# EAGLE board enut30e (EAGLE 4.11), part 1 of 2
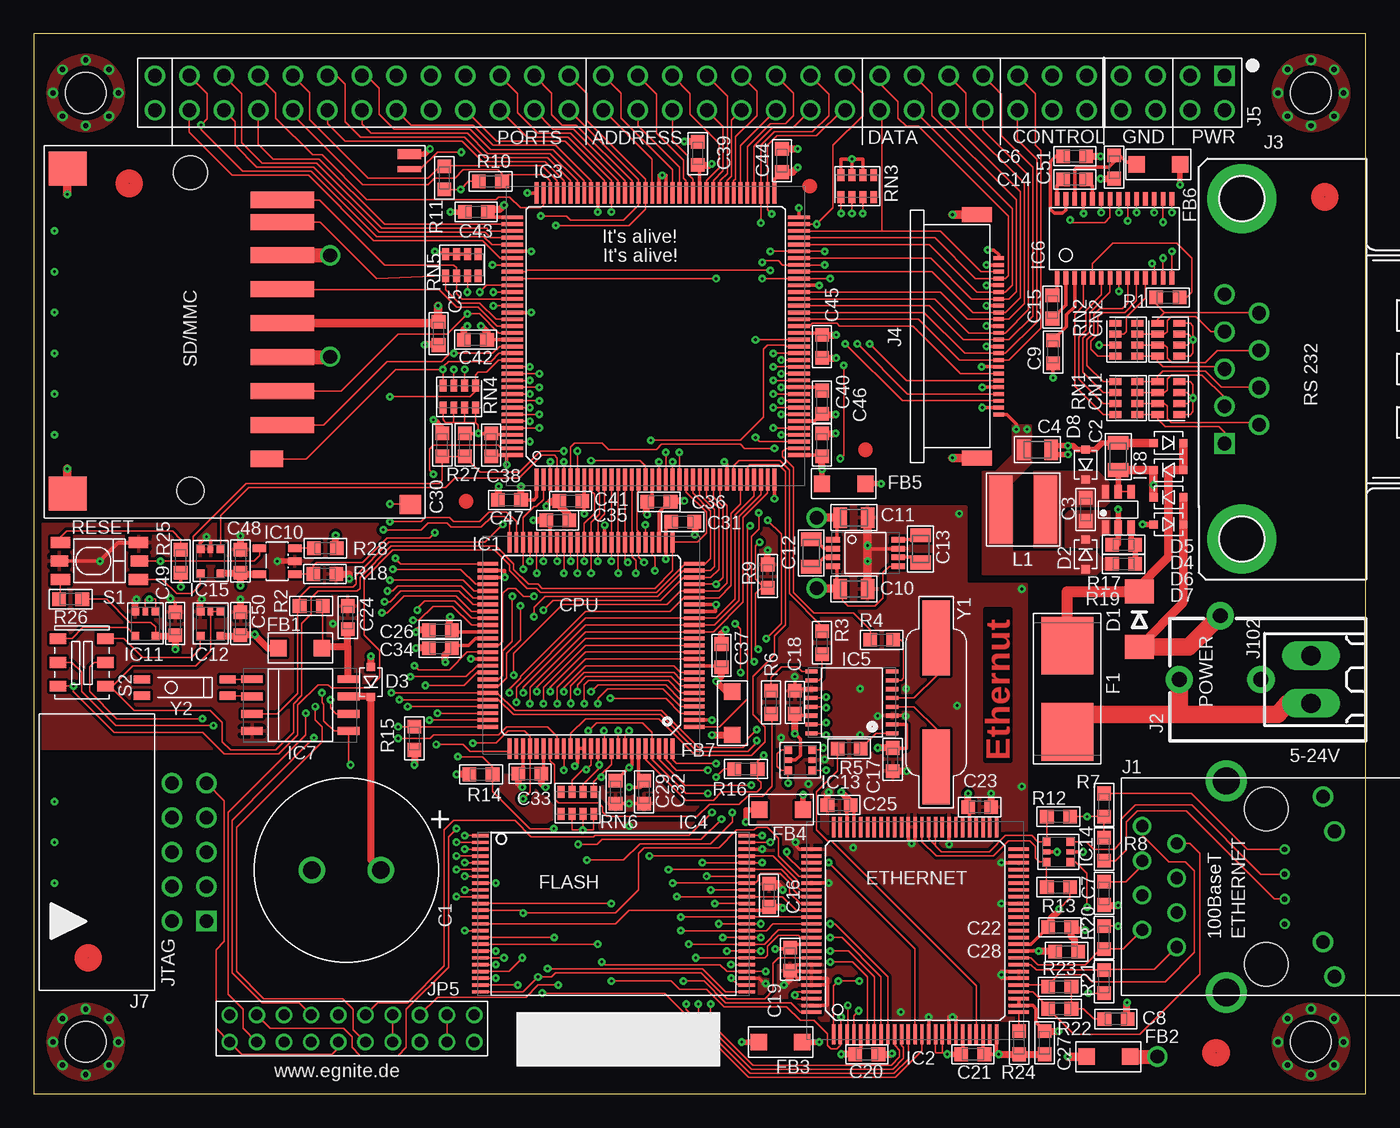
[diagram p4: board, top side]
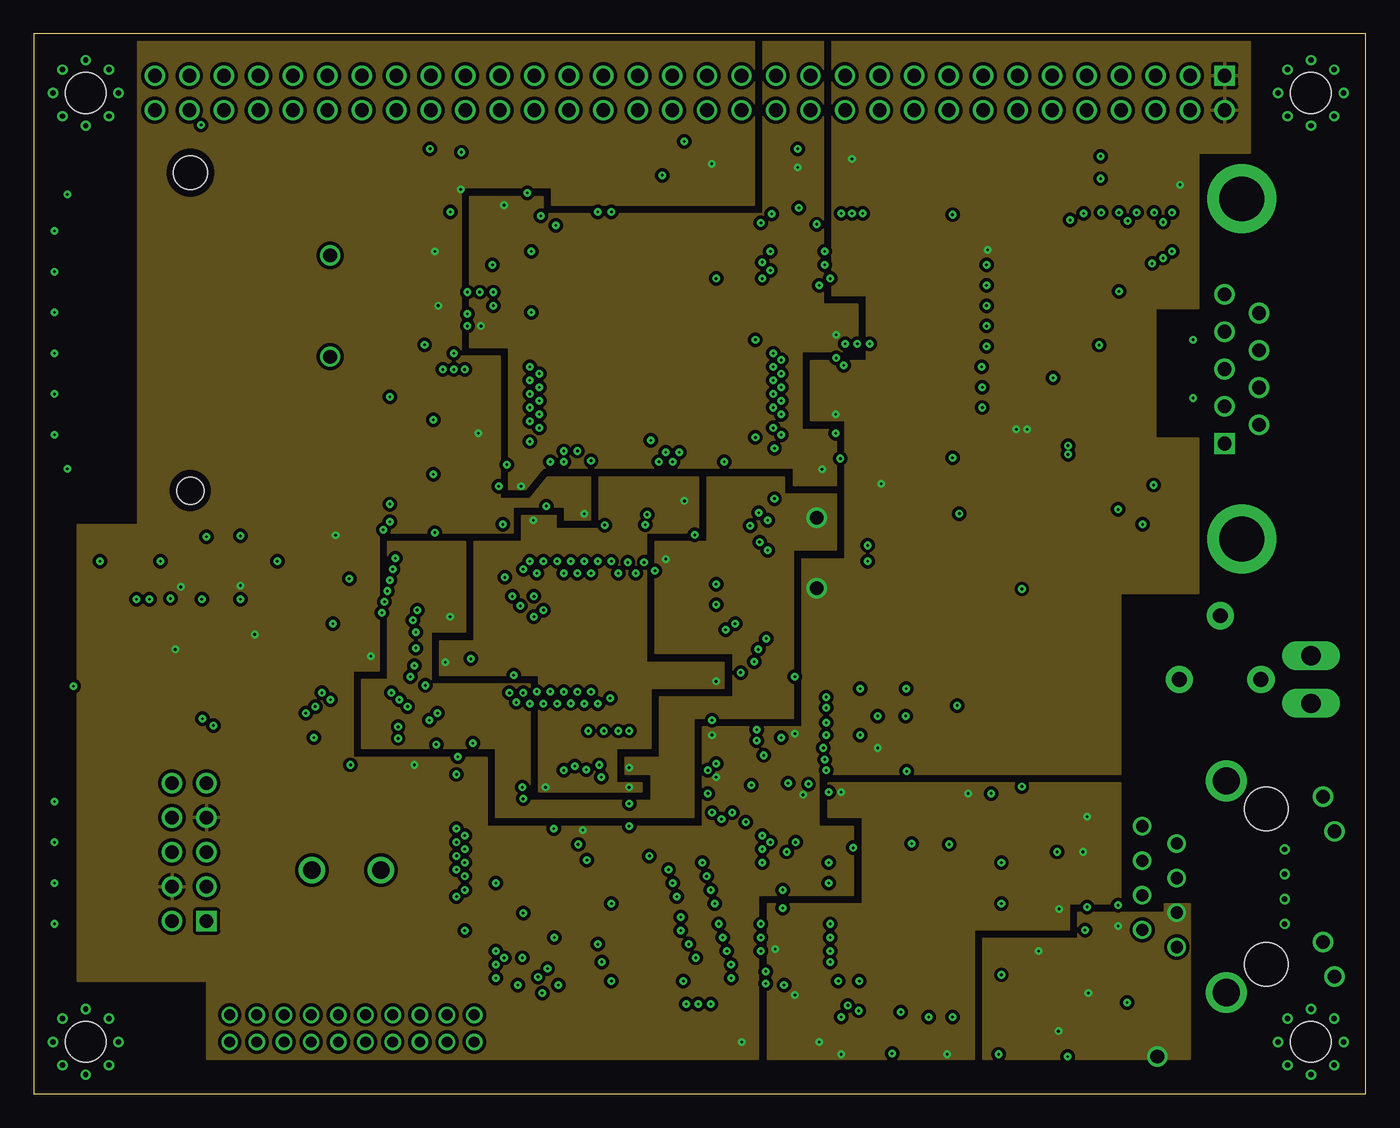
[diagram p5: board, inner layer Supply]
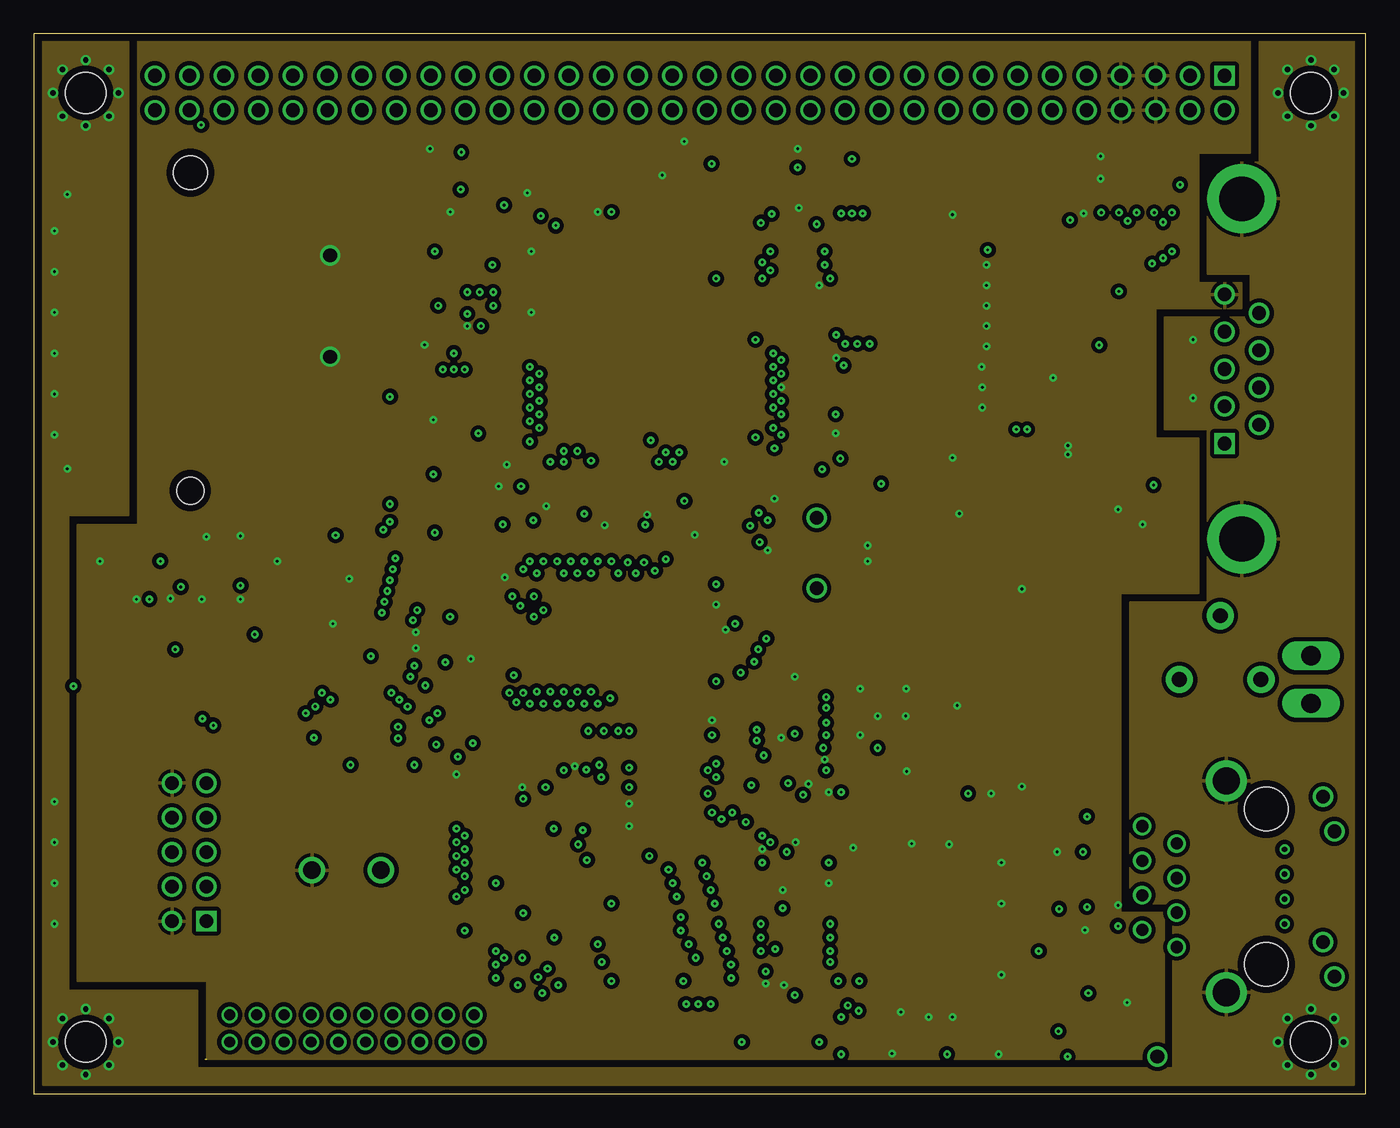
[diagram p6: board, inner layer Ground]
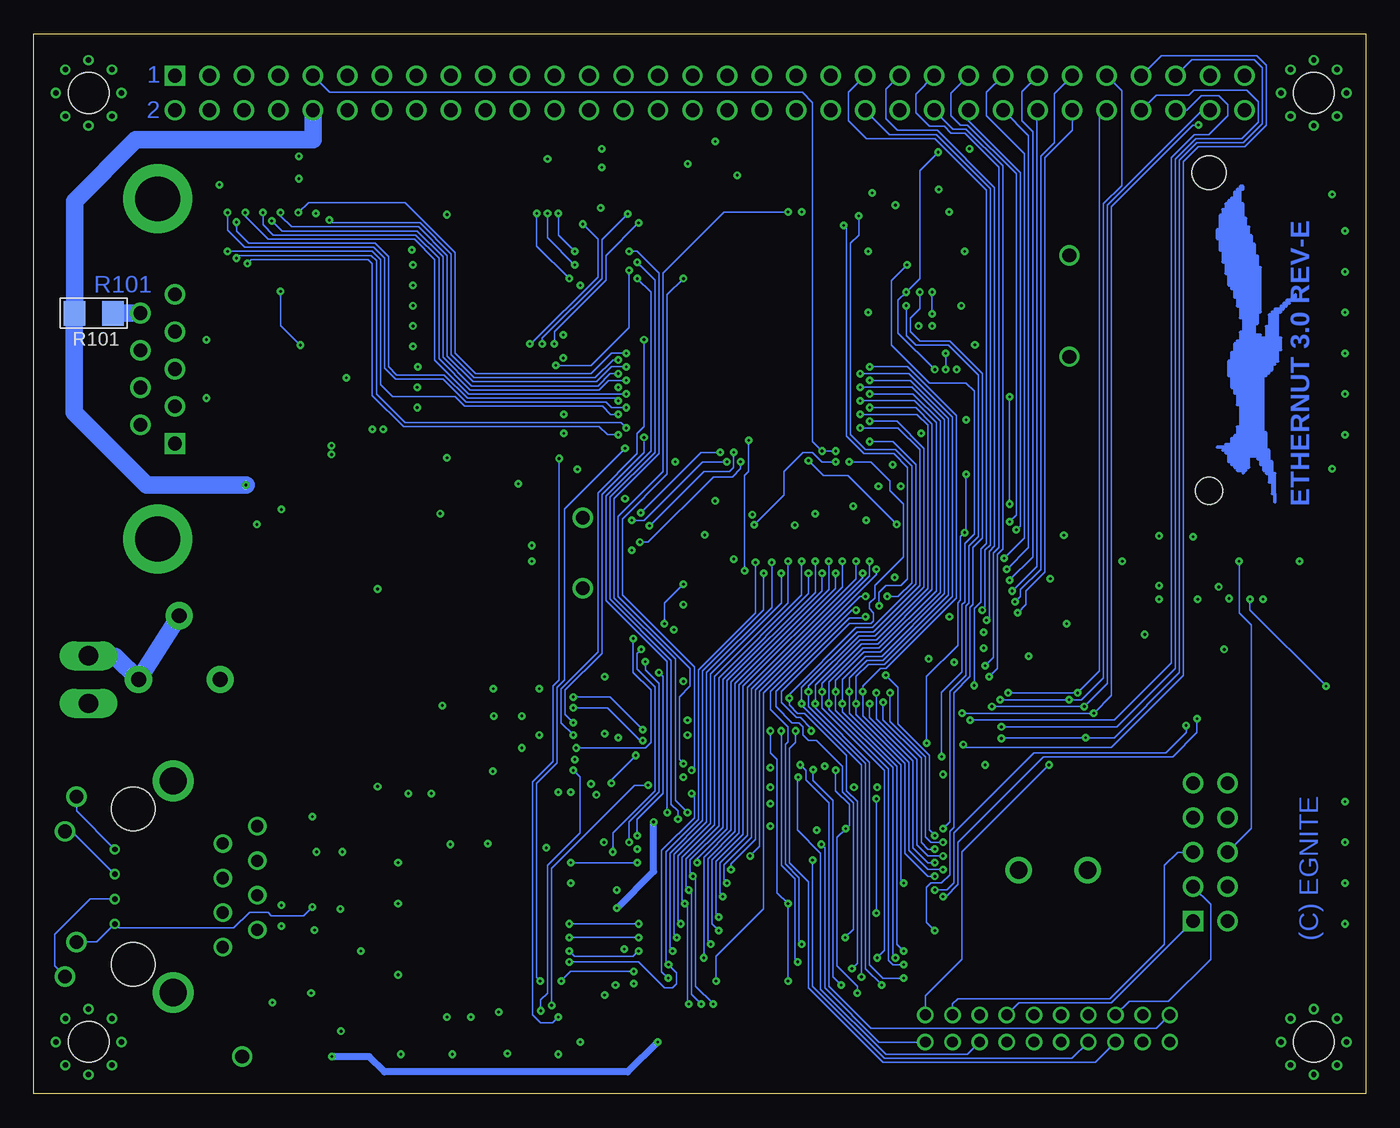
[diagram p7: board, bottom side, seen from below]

Size 98 x 78 mm. Coordinates in mm from the lower left corner, seen from the top.
Outline: 0,0 98,0 98,78 0,78 0,0
Copper layers (1*2+15*16): Top 0.035mm / dielectric 0.5mm / Supply 0.035mm / dielectric 0.5mm / Ground 0.035mm / dielectric 0.5mm / Bottom 0.035mm
Design rules "default": minimum track width 5mil, minimum drill 0.2mm, track to track 6mil, track to pad 6mil, pad to pad 8mil, via to via 8mil, smd to smd 8mil, copper to edge 20mil, drill to drill 12mil, minimum pad ring 8mil, minimum via ring 7mil, stop-mask expansion 0mil, vias tented up to drill 0.3mm, thermal gap 10mil
Net classes: 1 Supply1A: width 0.61 mm; 4 Ground: width 0.406 mm
Holes 3 mm at 3.81,73.66 93.98,73.66 3.81,3.81 93.98,3.81

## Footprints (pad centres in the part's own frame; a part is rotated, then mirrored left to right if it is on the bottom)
CDL13_5 = drill 1.3 pad 1.3 round: + 2.54,0; - -2.54,0
C0805 = smd 1 x 1.5: 1 -1,0; 2 1,0
C0603 = smd 1 x 1: 1 -0.85,0; 2 0.85,0
NCA1206 = smd 0.508 x 0.889: 1 -1.2,-0.805; 2 -0.4,-0.805; 3 0.4,-0.805; 4 1.2,-0.805; 5 1.2,0.805; 6 0.4,0.805; 7 -0.4,0.805; 8 -1.2,0.805
SMB = smd 1.778 x 2.159: A 2.032,0; C -2.032,0
SOD323 = smd 0.6 x 0.6: A 1.1,0; C -1.1,0
OMNI-BLOK = smd 4.242 x 3.81: 1 -3.175,0; 2 3.175,0
BLM31 = smd 1.2 x 1.2: 1 -1.6,0; 2 1.6,0
TQFP100 = smd 0.28 x 1.5: 1 -6,-7.6; 2 -5.5,-7.6; 3 -5,-7.6; 4 -4.5,-7.6; 5 -4,-7.6; 6 -3.5,-7.6; 7 -3,-7.6; 8 -2.5,-7.6; 9 -2,-7.6; 10 -1.5,-7.6; 11 -1,-7.6; 12 -0.5,-7.6; 13 0,-7.6; 14 0.5,-7.6; 15 1,-7.6; 16 1.5,-7.6; 17 2,-7.6; 18 2.5,-7.6; 19 3,-7.6; 20 3.5,-7.6; 21 4,-7.6; 22 4.5,-7.6; 23 5,-7.6; 24 5.5,-7.6; 25 6,-7.6; 51 6,7.6; 52 5.5,7.6; 53 5,7.6; 54 4.5,7.6; 55 4,7.6; 56 3.5,7.6; 57 3,7.6; 58 2.5,7.6; 59 2,7.6; 60 1.5,7.6; 61 1,7.6; 62 0.5,7.6; 63 0,7.6; 64 -0.5,7.6; 65 -1,7.6; 66 -1.5,7.6; 67 -2,7.6; 68 -2.5,7.6; 69 -3,7.6; 70 -3.5,7.6; 71 -4,7.6; 72 -4.5,7.6; 73 -5,7.6; 74 -5.5,7.6; 75 -6,7.6 | smd 1.5 x 0.28: 26 7.6,-6; 27 7.6,-5.5; 28 7.6,-5; 29 7.6,-4.5; 30 7.6,-4; 31 7.6,-3.5; 32 7.6,-3; 33 7.6,-2.5; 34 7.6,-2; 35 7.6,-1.5; 36 7.6,-1; 37 7.6,-0.5; 38 7.6,0; 39 7.6,0.5; 40 7.6,1; 41 7.6,1.5; 42 7.6,2; 43 7.6,2.5; 44 7.6,3; 45 7.6,3.5; 46 7.6,4; 47 7.6,4.5; 48 7.6,5; 49 7.6,5.5; 50 7.6,6; 76 -7.6,6; 77 -7.6,5.5; 78 -7.6,5; 79 -7.6,4.5; 80 -7.6,4; 81 -7.6,3.5; 82 -7.6,3; 83 -7.6,2.5; 84 -7.6,2; 85 -7.6,1.5; 86 -7.6,1; 87 -7.6,0.5; 88 -7.6,0; 89 -7.6,-0.5; 90 -7.6,-1; 91 -7.6,-1.5; 92 -7.6,-2; 93 -7.6,-2.5; 94 -7.6,-3; 95 -7.6,-3.5; 96 -7.6,-4; 97 -7.6,-4.5; 98 -7.6,-5; 99 -7.6,-5.5; 100 -7.6,-6
LQFP100 = smd 0.25 x 1.5: 1 -6,-7.625; 2 -5.5,-7.625; 3 -5,-7.625; 4 -4.5,-7.625; 5 -4,-7.625; 6 -3.5,-7.625; 7 -3,-7.625; 8 -2.5,-7.625; 9 -2,-7.625; 10 -1.5,-7.625; 11 -1,-7.625; 12 -0.5,-7.625; 13 0,-7.625; 14 0.5,-7.625; 15 1,-7.625; 16 1.5,-7.625; 17 2,-7.625; 18 2.5,-7.625; 19 3,-7.625; 20 3.5,-7.625; 21 4,-7.625; 22 4.5,-7.625; 23 5,-7.625; 24 5.5,-7.625; 25 6,-7.625; 51 6,7.625; 52 5.5,7.625; 53 5,7.625; 54 4.5,7.625; 55 4,7.625; 56 3.5,7.625; 57 3,7.625; 58 2.5,7.625; 59 2,7.625; 60 1.5,7.625; 61 1,7.625; 62 0.5,7.625; 63 0,7.625; 64 -0.5,7.625; 65 -1,7.625; 66 -1.5,7.625; 67 -2,7.625; 68 -2.5,7.625; 69 -3,7.625; 70 -3.5,7.625; 71 -4,7.625; 72 -4.5,7.625; 73 -5,7.625; 74 -5.5,7.625; 75 -6,7.625 | smd 1.5 x 0.25: 26 7.625,-6; 27 7.625,-5.5; 28 7.625,-5; 29 7.625,-4.5; 30 7.625,-4; 31 7.625,-3.5; 32 7.625,-3; 33 7.625,-2.5; 34 7.625,-2; 35 7.625,-1.5; 36 7.625,-1; 37 7.625,-0.5; 38 7.625,0; 39 7.625,0.5; 40 7.625,1; 41 7.625,1.5; 42 7.625,2; 43 7.625,2.5; 44 7.625,3; 45 7.625,3.5; 46 7.625,4; 47 7.625,4.5; 48 7.625,5; 49 7.625,5.5; 50 7.625,6; 76 -7.625,6; 77 -7.625,5.5; 78 -7.625,5; 79 -7.625,4.5; 80 -7.625,4; 81 -7.625,3.5; 82 -7.625,3; 83 -7.625,2.5; 84 -7.625,2; 85 -7.625,1.5; 86 -7.625,1; 87 -7.625,0.5; 88 -7.625,0; 89 -7.625,-0.5; 90 -7.625,-1; 91 -7.625,-1.5; 92 -7.625,-2; 93 -7.625,-2.5; 94 -7.625,-3; 95 -7.625,-3.5; 96 -7.625,-4; 97 -7.625,-4.5; 98 -7.625,-5; 99 -7.625,-5.5; 100 -7.625,-6
XC95_TQ144 = smd 0.28 x 1.6: 1 -8.75,-10.55; 2 -8.25,-10.55; 3 -7.75,-10.55; 4 -7.25,-10.55; 5 -6.75,-10.55; 6 -6.25,-10.55; 7 -5.75,-10.55; 8 -5.25,-10.55; 9 -4.75,-10.55; 10 -4.25,-10.55; 11 -3.75,-10.55; 12 -3.25,-10.55; 13 -2.75,-10.55; 14 -2.25,-10.55; 15 -1.75,-10.55; 16 -1.25,-10.55; 17 -0.75,-10.55; 18 -0.25,-10.55; 19 0.25,-10.55; 20 0.75,-10.55; 21 1.25,-10.55; 22 1.75,-10.55; 23 2.25,-10.55; 24 2.75,-10.55; 25 3.25,-10.55; 26 3.75,-10.55; 27 4.25,-10.55; 28 4.75,-10.55; 29 5.25,-10.55; 30 5.75,-10.55; 31 6.25,-10.55; 32 6.75,-10.55; 33 7.25,-10.55; 34 7.75,-10.55; 35 8.25,-10.55; 36 8.75,-10.55; 73 8.75,10.55; 74 8.25,10.55; 75 7.75,10.55; 76 7.25,10.55; 77 6.75,10.55; 78 6.25,10.55; 79 5.75,10.55; 80 5.25,10.55; 81 4.75,10.55; 82 4.25,10.55; 83 3.75,10.55; 84 3.25,10.55; 85 2.75,10.55; 86 2.25,10.55; 87 1.75,10.55; 88 1.25,10.55; 89 0.75,10.55; 90 0.25,10.55; 91 -0.25,10.55; 92 -0.75,10.55; 93 -1.25,10.55; 94 -1.75,10.55; 95 -2.25,10.55; 96 -2.75,10.55; 97 -3.25,10.55; 98 -3.75,10.55; 99 -4.25,10.55; 100 -4.75,10.55; 101 -5.25,10.55; 102 -5.75,10.55; 103 -6.25,10.55; 104 -6.75,10.55; 105 -7.25,10.55; 106 -7.75,10.55; 107 -8.25,10.55; 108 -8.75,10.55 | smd 1.6 x 0.28: 37 10.55,-8.75; 38 10.55,-8.25; 39 10.55,-7.75; 40 10.55,-7.25; 41 10.55,-6.75; 42 10.55,-6.25; 43 10.55,-5.75; 44 10.55,-5.25; 45 10.55,-4.75; 46 10.55,-4.25; 47 10.55,-3.75; 48 10.55,-3.25; 49 10.55,-2.75; 50 10.55,-2.25; 51 10.55,-1.75; 52 10.55,-1.25; 53 10.55,-0.75; 54 10.55,-0.25; 55 10.55,0.25; 56 10.55,0.75; 57 10.55,1.25; 58 10.55,1.75; 59 10.55,2.25; 60 10.55,2.75; 61 10.55,3.25; 62 10.55,3.75; 63 10.55,4.25; 64 10.55,4.75; 65 10.55,5.25; 66 10.55,5.75; 67 10.55,6.25; 68 10.55,6.75; 69 10.55,7.25; 70 10.55,7.75; 71 10.55,8.25; 72 10.55,8.75; 109 -10.55,8.75; 110 -10.55,8.25; 111 -10.55,7.75; 112 -10.55,7.25; 113 -10.55,6.75; 114 -10.55,6.25; 115 -10.55,5.75; 116 -10.55,5.25; 117 -10.55,4.75; 118 -10.55,4.25; 119 -10.55,3.75; 120 -10.55,3.25; 121 -10.55,2.75; 122 -10.55,2.25; 123 -10.55,1.75; 124 -10.55,1.25; 125 -10.55,0.75; 126 -10.55,0.25; 127 -10.55,-0.25; 128 -10.55,-0.75; 129 -10.55,-1.25; 130 -10.55,-1.75; 131 -10.55,-2.25; 132 -10.55,-2.75; 133 -10.55,-3.25; 134 -10.55,-3.75; 135 -10.55,-4.25; 136 -10.55,-4.75; 137 -10.55,-5.25; 138 -10.55,-5.75; 139 -10.55,-6.25; 140 -10.55,-6.75; 141 -10.55,-7.25; 142 -10.55,-7.75; 143 -10.55,-8.25; 144 -10.55,-8.75
TSOP48 = smd 0.25 x 1.2: 1 -5.75,-9.8; 2 -5.25,-9.8; 3 -4.75,-9.8; 4 -4.25,-9.8; 5 -3.75,-9.8; 6 -3.25,-9.8; 7 -2.75,-9.8; 8 -2.25,-9.8; 9 -1.75,-9.8; 10 -1.25,-9.8; 11 -0.75,-9.8; 12 -0.25,-9.8; 13 0.25,-9.8; 14 0.75,-9.8; 15 1.25,-9.8; 16 1.75,-9.8; 17 2.25,-9.8; 18 2.75,-9.8; 19 3.25,-9.8; 20 3.75,-9.8; 21 4.25,-9.8; 22 4.75,-9.8; 23 5.25,-9.8; 24 5.75,-9.8; 25 5.75,9.8; 26 5.25,9.8; 27 4.75,9.8; 28 4.25,9.8; 29 3.75,9.8; 30 3.25,9.8; 31 2.75,9.8; 32 2.25,9.8; 33 1.75,9.8; 34 1.25,9.8; 35 0.75,9.8; 36 0.25,9.8; 37 -0.25,9.8; 38 -0.75,9.8; 39 -1.25,9.8; 40 -1.75,9.8; 41 -2.25,9.8; 42 -2.75,9.8; 43 -3.25,9.8; 44 -3.75,9.8; 45 -4.25,9.8; 46 -4.75,9.8; 47 -5.25,9.8; 48 -5.75,9.8
TSSOP16 = smd 0.3 x 0.9: 1 -2.275,-2.97; 2 -1.625,-2.97; 3 -0.975,-2.97; 4 -0.325,-2.97; 5 0.325,-2.97; 6 0.975,-2.97; 7 1.625,-2.97; 8 2.275,-2.97; 9 2.275,2.97; 10 1.625,2.97; 11 0.975,2.97; 12 0.325,2.97; 13 -0.325,2.97; 14 -0.975,2.97; 15 -1.625,2.97; 16 -2.275,2.97
TSSOP28 = smd 0.35 x 1: 1 -4.225,-2.918; 2 -3.575,-2.918; 3 -2.925,-2.918; 4 -2.275,-2.918; 5 -1.625,-2.918; 6 -0.975,-2.918; 7 -0.325,-2.918; 8 0.325,-2.918; 9 0.975,-2.918; 10 1.625,-2.918; 11 2.275,-2.918; 12 2.925,-2.918; 13 3.575,-2.918; 14 4.225,-2.918; 15 4.225,2.918; 16 3.575,2.918; 17 2.925,2.918; 18 2.275,2.918; 19 1.625,2.918; 20 0.975,2.918; 21 0.325,2.918; 22 -0.325,2.918; 23 -0.975,2.918; 24 -1.625,2.918; 25 -2.275,2.918; 26 -2.925,2.918; 27 -3.575,2.918; 28 -4.225,2.918
SOIC-8-209 = smd 0.58 x 1.6: 1 -1.905,-3.556; 2 -0.635,-3.556; 3 0.635,-3.556; 4 1.905,-3.556; 5 1.905,3.556; 6 0.635,3.556; 7 -0.635,3.556; 8 -1.905,3.556
TSOT-23-6 = smd 0.54 x 1: 1 -0.95,-1.31; 2 0,-1.31; 3 0.95,-1.31; 4 0.95,1.31; 5 0,1.31; 6 -0.95,1.31
MSOP-8 = smd 0.41 x 1.02: 1 -0.975,-2.4; 2 -0.325,-2.4; 3 0.325,-2.4; 4 0.975,-2.4; 5 0.975,2.4; 6 0.325,2.4; 7 -0.325,2.4; 8 -0.975,2.4
SOT23-5L = smd 0.55 x 0.99: 1 -0.95,-1.3; 2 0,-1.3; 3 0.95,-1.3; 4 0.95,1.3; 5 -0.95,1.3
SOT353 = smd 0.6 x 0.6: 1 -0.75,-0.9; 3 0.75,-0.9; 4 0.75,0.9; 5 -0.75,0.9 | smd 0.4 x 0.6: 2 0,-0.9
SOT363 = smd 0.6 x 0.6: 1 -0.75,-0.9; 3 0.75,-0.9; 4 0.75,0.9; 6 -0.75,0.9 | smd 0.4 x 0.6: 2 0,-0.9; 5 0,0.9
RJLD-043TC = drill 0.9 round: 1 -6.7,-4.445; 2 -9.24,-3.175; 3 -6.7,-1.905; 4 -9.24,-0.635; 5 -6.7,0.635; 6 -9.24,1.905; 7 -6.7,3.175; 8 -9.24,4.445 | drill 1 round: 9 4.9,-6.61; 10 4.06,-4.07; 11 4.9,4.07; 12 4.06,6.61 | drill 2 round: S1 -3.05,-7.79; S2 -3.05,7.79 | hole 3.2: -0.102,-5.715; -0.102,5.715
TDC-002-3 = drill 1.1 pad 2 round: 1 -6.5,0; 2 -0.5,0; 3 -3.5,4.7
M09HP = drill 1.016 square: 1 -5.486,5.08 | drill 1.016 round: 2 -2.743,5.08; 3 0,5.08; 4 2.743,5.08; 5 5.486,5.08; 6 -4.115,2.54; 7 -1.372,2.54; 8 1.372,2.54; 9 4.115,2.54 | drill 3.302 pad 5.08 round: G1 -12.522,3.81; G2 12.522,3.81
FFC-52437 = smd 0.29 x 0.8: 1 -5.75,3.5; 2 -5.25,3.5; 3 -4.75,3.5; 4 -4.25,3.5; 5 -3.75,3.5; 6 -3.25,3.5; 7 -2.75,3.5; 8 -2.25,3.5; 9 -1.75,3.5; 10 -1.25,3.5; 11 -0.75,3.5; 12 -0.25,3.5; 13 0.25,3.5; 14 0.75,3.5; 15 1.25,3.5; 16 1.75,3.5; 17 2.25,3.5; 18 2.75,3.5; 19 3.25,3.5; 20 3.75,3.5; 21 4.25,3.5; 22 4.75,3.5; 23 5.25,3.5; 24 5.75,3.5 | smd 1.1 x 2.2: G1 -8.95,1.9; G2 8.95,1.9
NUTEXP = drill 1 square: 1 39.37,1.27 | drill 1 round: 2 39.37,-1.27; 3 36.83,1.27; 4 36.83,-1.27; 5 34.29,1.27; 6 34.29,-1.27; 7 31.75,1.27; 8 31.75,-1.27; 9 29.21,1.27; 10 29.21,-1.27; 11 26.67,1.27; 12 26.67,-1.27; 13 24.13,1.27; 14 24.13,-1.27; 15 21.59,1.27; 16 21.59,-1.27; 17 19.05,1.27; 18 19.05,-1.27; 19 16.51,1.27; 20 16.51,-1.27; 21 13.97,1.27; 22 13.97,-1.27; 23 11.43,1.27; 24 11.43,-1.27; 25 8.89,1.27; 26 8.89,-1.27; 27 6.35,1.27; 28 6.35,-1.27; 29 3.81,1.27; 30 3.81,-1.27; 31 1.27,1.27; 32 1.27,-1.27; 33 -1.27,1.27; 34 -1.27,-1.27; 35 -3.81,1.27; 36 -3.81,-1.27; 37 -6.35,1.27; 38 -6.35,-1.27; 39 -8.89,1.27; 40 -8.89,-1.27; 41 -11.43,1.27; 42 -11.43,-1.27; 43 -13.97,1.27; 44 -13.97,-1.27; 45 -16.51,1.27; 46 -16.51,-1.27; 47 -19.05,1.27; 48 -19.05,-1.27; 49 -21.59,1.27; 50 -21.59,-1.27; 51 -24.13,1.27; 52 -24.13,-1.27; 53 -26.67,1.27; 54 -26.67,-1.27; 55 -29.21,1.27; 56 -29.21,-1.27; 57 -31.75,1.27; 58 -31.75,-1.27; 59 -34.29,1.27; 60 -34.29,-1.27; 61 -36.83,1.27; 62 -36.83,-1.27; 63 -39.37,1.27; 64 -39.37,-1.27
FPS009-2700 = smd 4.7 x 1.2: 1 -3.51,6.85; 2 -3.51,4.35; 3 -3.51,1.85; 4 -3.51,-0.65; 5 -3.51,-3.15; 6 -3.51,-5.65; 7 -3.51,-8.08; 8 -3.51,-9.71 | smd 2.4 x 1.2: 9 -2.36,9.35 | smd 1.75 x 0.75: C -12.865,-13.09 | smd 1.75 x 0.45: CD -12.865,-11.965 | smd 2.8 x 2.5: CH1 12.29,11.91; CH2 12.29,-12 | smd 1.6 x 1.4: WP -12.94,12.71 | hole 2: 3.26,11.68 | hole 2.5: 3.26,-11.72
ML10A = drill 1 pad 1.422 square: 1 -5.08,-6.35 | drill 1 pad 1.422 round: 2 -5.08,-3.81; 3 -2.54,-6.35; 4 -2.54,-3.81; 5 0,-6.35; 6 0,-3.81; 7 2.54,-6.35; 8 2.54,-3.81; 9 5.08,-6.35; 10 5.08,-3.81
180-2 = drill 1.422 long: 1 -1.75,0; 2 1.75,0
JP10X2 = drill 0.8 round: 1 -9,-1; 2 -9,1; 3 -7,-1; 4 -7,1; 5 -5,-1; 6 -5,1; 7 -3,-1; 8 -3,1; 9 -1,-1; 10 -1,1; 11 1,-1; 12 1,1; 13 3,-1; 14 3,1; 15 5,-1; 16 5,1; 17 7,-1; 18 7,1; 19 9,-1; 20 9,1
MSS5131 = smd 5 x 1.7: 1 0,-1.65; 2 0,1.65
R0603 = smd 1 x 1: 1 -0.85,0; 2 0.85,0
R1206 = smd 1.6 x 1.803: 1 -1.422,0; 2 1.422,0
CAY16 = smd 0.508 x 0.889: 1 -1.2,-0.805; 2 -0.4,-0.805; 3 0.4,-0.805; 4 1.2,-0.805; 5 1.2,0.805; 6 0.4,0.805; 7 -0.4,0.805; 8 -1.2,0.805
PTS-026 = smd 1.45 x 0.8: A1 2.875,-1.35; A2 2.875,1.35; C1 -2.875,-1.35; C2 -2.875,1.35 | smd 1.3 x 0.8: S1 2.95,0; S2 -2.95,0
CAS-D20A1 = smd 0.8 x 1.2: 1 -1.75,-1.75; 2 0,-1.75; 3 1.75,-1.75; 4 -1.75,1.75; 5 0,1.75; 6 1.75,1.75
HC49SM = smd 5.5 x 2: 1 -4.75,0; 2 4.75,0
MC-146 = smd 1.2 x 0.6: 1 -3.15,-0.6; 2 3.15,-0.6; 3 3.15,0.6; 4 -3.15,0.6

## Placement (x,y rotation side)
C1  0.1F  [CDL13_5]  23,16.45 0 top
C2  1u  [C0805]  79.8,46.9 90 top
C3  10n  [C0603]  77.4,43 90 top
C4  10u  [C0805]  73.85,47.4 0 top
C5  470n  [C0603]  29.78,55.95 270 top
C6  470n  [C0603]  76.6,69 0 top
C7  100n  [C0603]  78.75,14.75 270 top
C8  100n  [C0603]  79.62,5.5 0 top
C9  470n  [C0603]  75,54.6 270 top
C10  10u  [C0805]  60.35,37.15 0 top
C11  10u  [C0805]  60.35,42.4 0 top
C12  1u  [C0805]  57.2,39.8 90 top
C13  1u  [C0805]  65.25,40.1 90 top
C14  100n  [C0603]  76.6,67.3 0 top
C15  470n  [C0603]  74.95,57.9 270 top
C16  100n  [C0603]  54.1,14.6 90 top
C17  100n  [C0603]  63.2,24.6 270 top
C18  100n  [C0603]  56,28.8 90 top
C19  100n  [C0603]  55.65,9.9 270 top
C20  100n  [C0603]  61.3,2.9 0 top
C21  100n  [C0603]  69.1,2.9 0 top
C22  100n  [C0603]  75.5,12.25 0 top
C23  100n  [C0603]  69.6,21.1 0 top
C24  100n  [C0603]  23.1,35.05 90 top
C25  100n  [C0603]  59.25,21.25 180 top
C26  100n  [C0603]  29.9,34.12 180 top
C27  100n  [C0603]  74.38,3.75 270 top
C28  100n  [C0603]  76,10.45 0 top
C29  100n  [C0603]  42.8,22.2 270 top
C30  100n  [C0603]  30.05,47.75 90 top
C31  100n  [C0603]  47.75,42.1 0 top
C32  100n  [C0603]  44.9,22.2 270 top
C33  100n  [C0603]  36.5,23.55 180 top
C34  100n  [C0603]  29.9,32.8 180 top
C35  100n  [C0603]  38.55,42.2 0 top
C36  100n  [C0603]  46,43.58 180 top
C37  100n  [C0603]  50.6,32.25 90 top
C38  100n  [C0603]  33.65,47.75 270 top
C39  100n  [C0603]  48.85,69.2 90 top
C40  100n  [C0603]  58,50.9 90 top
C41  100n  [C0603]  39.5,43.62 180 top
C42  100n  [C0603]  32.5,55.5 180 top
C43  100n  [C0603]  32.55,64.9 180 top
C44  100n  [C0603]  55.05,68.67 90 top
C45  100n  [C0603]  58,55 270 top
C46  100n  [C0603]  58,47.75 90 top
C47  100n  [C0603]  35,43.7 180 top
C48  100n  [C0603]  15.2,39.2 90 top
C49  100n  [C0603]  10.4,34.6 90 top
C50  100n  [C0603]  15.2,34.6 90 top
C51  100n  [C0603]  79.5,68.2 270 top
CN1  220p  [NCA1206]  83.5,51.2 90 top
CN2  220p  [NCA1206]  83.5,55.5 270 top
D1  SM6T24CA  [SMB]  81.35,34.92 270 top
D2  PMEG3005AEA  [SOD323]  77.4,39.7 270 top
D3  PMEG2005AEA  [SOD323]  24.8,30.3 90 top
D4  PMEG3005AEA  [SOD323]  83.5,45.9 0 top
D5  PMEG3005AEA  [SOD323]  83.5,47.9 180 top
D6  PMEG3005AEA  [SOD323]  83.5,43.9 0 top
D7  PMEG3005AEA  [SOD323]  83.5,41.9 180 top
D8  PMEG3005AEA  [SOD323]  77.4,46.3 90 top
F1  1A  [OMNI-BLOK]  76.05,29.8 90 top
FB1  BLM31AJ601  [BLM31]  19.6,32.8 0 top
FB2  BLM31AJ601  [BLM31]  79.08,2.73 180 top
FB3  BLM31AJ601  [BLM31]  54.95,3.8 180 top
FB4  BLM31AJ601  [BLM31]  55,20.9 0 top
FB5  BLM31AJ601  [BLM31]  59.6,44.9 0 top
FB6  BLM31AJ601  [BLM31]  82.75,68.4 0 top
FB7  BLM31AJ601  [BLM31]  51.4,28 270 top
FM1  FIDUCIAL-2MM  [FIDUCIAL-2MM]  4,10 0 top
FM2  FIDUCIAL-2MM  [FIDUCIAL-2MM]  87,3 0 top
FM3  FIDUCIAL-2MM  [FIDUCIAL-2MM]  7,67 0 top
FM4  FIDUCIAL-2MM  [FIDUCIAL-2MM]  95,66 0 top
IC1  AT91R40008  [TQFP100]  41,33 90 top
IC2  DM9000E  [LQFP100]  64.85,12 0 top
IC3  XC95144XLTQ144  [XC95_TQ144]  45.75,55.75 0 top
IC4  AT49BV322A-70TI  [TSOP48]  42.65,13.25 270 top
IC5  CY22393  [TSSOP16]  60.2,28.8 90 top
IC6  MAX3243UI  [TSSOP28]  79.52,62.95 0 top
IC7  X1286A8  [SOIC-8-209]  19.6,28.6 270 top
IC8  LT1616  [TSOT-23-6]  79.8,43 0 top
IC9  LM2788MM-1.8  [MSOP-8]  61.2,39.8 270 top
IC10  MIC2775-46BM5  [SOT23-5L]  17.9,39.2 90 top
IC11  74LVC1G00GW  [SOT353]  8.2,34.6 180 top
IC12  74LVC1G00GW  [SOT353]  13,34.6 180 top
IC13  NC7WZ07P6X  [SOT363]  56.4,24.55 90 top
IC14  NC7WZ07P6X  [SOT363]  75.4,17.8 270 top
IC15  74LVC1G125GW  [SOT353]  13,39.2 180 top
J1  RJLD-043TC  [RJLD-043TC]  90.81,15.24 0 top
J2  2mm  [TDC-002-3]  90.81,30.48 0 top
J3  M09HP  [M09HP]  92.71,53.34 90 top
J4  FCC24  [FFC-52437]  67.5,55.75 270 top
J5  [NUTEXP]  48.26,73.66 0 top
J6  FPS009-2700  [FPS009-2700]  14.77,56.07 180 top
J7  [ML10A]  6.35,17.78 90 top
J102  [180-2]  93.98,30.48 90 top
JP5  JP10X2  [JP10X2]  23.4,4.8 180 top
L1  10u  [MSS5131]  72.8,43 270 top
LOGO  [LOGO]  5.17,43.52 90 bottom
R1  0  [R0603]  83.45,58.6 0 top
R2  10k  [R0603]  20.4,35.9 0 top
R3  22  [R0603]  58,33.2 90 top
R4  22  [R0603]  62.4,33.4 180 top
R5  22  [R0603]  60,25.4 180 top
R6  22  [R0603]  54.25,28.8 270 top
R7  180  [R0603]  78.75,21.25 270 top
R8  180  [R0603]  78.75,18 90 top
R9  1k  [R0603]  54,38.1 270 top
R10  10k  [R0603]  33.6,67.15 0 top
R11  10k  [R0603]  30.2,67.4 90 top
R12  10k  [R0603]  75.4,20.4 0 top
R13  10k  [R0603]  75.4,15.2 0 top
R14  10k  [R0603]  32.9,23.5 0 top
R15  100k  [R0603]  28,26.15 90 top
R16  10k  [R0603]  52.4,23.9 0 top
R17  10k 1%  [R0603]  80.2,40.4 0 top
R18  100k  [R0603]  21.4,38.25 0 top
R19  16.5k 1%  [R0603]  80.2,39 180 top
R20  50 1%  [R0603]  78.75,11.5 90 top
R21  50 1%  [R0603]  78.75,8.25 270 top
R22  50 1%  [R0603]  75.5,6.25 180 top
R23  50 1%  [R0603]  75.5,7.88 180 top
R24  6.8k 1%  [R0603]  72.5,3.75 90 top
R25  180  [R0603]  10.8,39.2 270 top
R26  180  [R0603]  2.7,36.4 0 top
R27  10k  [R0603]  31.7,47.75 90 top
R28  100k  [R0603]  21.45,40.15 0 top
R101  0  [R1206]  93.6,57.45 180 bottom
RN1  22  [CAY16]  80.4,51.2 270 top
RN2  22  [CAY16]  80.4,55.5 270 top
RN3  100k  [CAY16]  60.6,66.8 0 top
RN4  10k  [CAY16]  31.3,51.3 180 top
RN5  10k  [CAY16]  31.5,61 0 top
RN6  100k  [CAY16]  40,21.4 180 top
S1  SW-LED  [PTS-026]  4.82,39.21 180 top
S2  CAS-D20A1  [CAS-D20A1]  3.52,31.74 270 top
U$10  [MARK1]  31.8,43.6 0 top
U$13  [MARK1]  57.1,66.8 0 top
U$14  [MARK1]  61.2,47.4 0 top
Y1  25MHz  [HC49SM]  66.4,28.8 270 top
Y2  32.768kHz  [MC-146]  11.1,29.9 180 top

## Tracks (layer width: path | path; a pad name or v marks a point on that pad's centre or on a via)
A0  (via drill 0.2)
  Top 0.127: v52.7,41.8 52.5,41.6 52.5,29.05 50.45,27 IC1.1 | v46.5,47.2 46.5,47.15 | 46.5,47.15 IC3.20 | 46.5,47.15
  Bottom 0.127: v46.5,47.2 46.5,46.1 46.8,45.8 48.7,45.8 v52.7,41.8
A1  (via drill 0.2)
  Top 0.127: v36.5,48 IC3.142 | IC4.25 50.9,7.5 49.2,9.2 v37.8,9.2 | IC1.3 47.6,28 46.5,29.1 v42.4,29.1
  Bottom 0.127: v37.8,9.2 37.4,9.6 37.4,21.5 38.2,22.3 38.2,24.9 41.3,28 41.8,28 42.4,28.6 v42.4,29.1 42.4,29.4 37.5,34.3 36.3,34.3 33.1,37.5 33.1,46.3 34.8,48 v36.5,48
A2  (via drill 0.2)
  Top 0.127: IC1.4 47.6,28.5 46.3,29.8 42.2,29.8 41.5,29.1 v41.5,28.7 | IC2.92 54.8,10 54.4,9.6 54.4,7.6 53.8,7 51,7 49.1,8.9 38.4,8.9 38.1,8.6 v37.1,8.6 36,7.5 IC4.24 | v37.2,49 37,49 | 37,49 IC3.140 | 37,49
  Bottom 0.127: v37.2,49 34.4,49 32.8,47.4 32.8,37.4 36.2,34 37.4,34 41.5,29.9 v41.5,28.7 41.5,28.6 37.1,24.2 v37.1,8.6
A3  (via drill 0.2)
  Top 0.127: 34.85,49.5 | 34.85,49.5 IC3.139 | v36.5,49.5 34.85,49.5 | IC4.23 v35.6,8 | v41,29.58 41.52,30.1 46.5,30.1 47.6,29 IC1.5
  Bottom 0.127: v36.5,49.5 34.5,49.5 32.5,47.5 32.5,37.3 36.1,33.7 37.3,33.7 41,30 v41,29.58 41,28.5 36.8,24.3 36.8,9.2 v35.6,8
A4  (via drill 0.2)
  Top 0.127: 34.95,50 | 34.95,50 IC3.138 | v37.2,50 34.95,50 | IC4.22 | IC4.22 v34,8.5 | v40.5,28.7 40.5,30.1 40.8,30.4 46.7,30.4 47.6,29.5 IC1.6
  Bottom 0.127: v37.2,50 33,50 32.2,49.2 32.2,37.2 36,33.4 37.2,33.4 40.5,30.1 v40.5,28.7 40.5,28.4 36.5,24.4 36.5,9.5 35.5,8.5 v34,8.5
A5  (via drill 0.2)
  Top 0.127: 34.9,50.5 | 34.9,50.5 IC3.137 | v36.5,50.5 34.9,50.5 | IC1.7 47.6,30 46.9,30.7 40.6,30.7 40,30.1 v40,29.58 | IC4.21 34.95,9 v35.95,10
  Bottom 0.127: v36.5,50.5 33.1,50.5 31.9,49.3 31.9,37.1 35.9,33.1 37.1,33.1 40,30.2 v40,29.58 40,28.4 35.4,23.8 35.4,10.55 v35.95,10
A6  (via drill 0.2)
  Top 0.127: 34.95,51 | 34.95,51 IC3.136 | v37.2,51 34.95,51 | IC4.20 | IC4.20 v34,9.5 | IC1.8 47.6,30.5 47.1,31 40.5,31 39.5,30 v39.5,28.72
  Bottom 0.127: v37.2,51 33.2,51 31.6,49.4 31.6,37 35.8,32.8 37,32.8 39.5,30.3 v39.5,28.72 39.5,28.3 35.1,23.9 35.1,9.8 34.8,9.5 v34,9.5
A7  (via drill 0.2)
  Top 0.127: IC4.19 v34.6,10 | v39,29.58 39,29.9 40.6,31.5 47.1,31.5 47.6,31 IC1.9 | v36.5,51.5 36.45,51.5 | 36.45,51.5 IC3.135 | 36.45,51.5
  Bottom 0.127: v36.5,51.5 33.3,51.5 31.3,49.5 31.3,36.9 35.7,32.5 36.9,32.5 39,30.4 v39,29.58 39,28.2 34.8,24 34.8,10.2 v34.6,10
A8  (via drill 0.2)
  Top 0.127: 34.95,52 | 34.95,52 IC3.134 | v37.2,52 34.95,52 | IC4.18 | IC4.18 v34,10.5 | IC1.11 40.6,32 38.5,29.9 v38.5,28.7
  Bottom 0.127: v37.2,52 33.4,52 31,49.6 31,36.8 35.6,32.2 36.8,32.2 38.5,30.5 v38.5,28.7 | v38.5,28.7 38.5,28.1 34.5,24.1 34.5,11 v34,10.5 | v38.5,28.7 38.5,29.8
A9  (via drill 0.2)
  Top 0.127: 34.95,52.5 | 34.95,52.5 IC3.133 | v36.5,52.5 34.95,52.5 | IC1.12 40.6,32.5 38,29.9 v38,29.6 | IC4.8 | IC4.8 v34,15.5
  Bottom 0.127: v36.5,52.5 33.5,52.5 30.7,49.7 30.7,36.7 35.5,31.9 36.7,31.9 38,30.6 v38,29.6 38,28 34.2,24.2 34.2,15.7 v34,15.5
A10  (via drill 0.2)
  Top 0.127: IC4.7 v31.7,16 | IC1.13 40.6,33 37.5,29.9 v37.5,28.7 | v37.2,53 37.05,53 | 37.05,53 IC3.132 | 37.05,53
  Bottom 0.127: v31.7,16 32.2,16 33.9,17.7 33.9,24.3 37.5,27.9 v37.5,28.7 37.5,30.7 36.6,31.6 35.4,31.6 30.4,36.6 30.4,49.8 33.6,53 v37.2,53
A11  (via drill 0.2)
  Top 0.127: 31.45,16.5 v31.1,16.5 | IC4.6 31.45,16.5 | 31.45,16.5 | v36.5,53.5 36.15,53.5 | 36.15,53.5 IC3.131 | 36.15,53.5 | IC1.14 40.6,33.5 37,29.9 v37,29.6
  Bottom 0.127: v31.1,16.5 32.2,16.5 33.6,17.9 33.6,24.4 37,27.8 v37,29.6 37,30 35.7,31.3 35.3,31.3 30.1,36.5 30.1,49.9 33.7,53.5 v36.5,53.5
A12  (via drill 0.2)
  Top 0.127: IC3.35 54,44.2 52.2,42.4 52.2,36.2 50,34 IC1.15 40.6,34 36.5,29.9 v36.5,28.7 | IC4.5 v31.7,17
  Bottom 0.127: v31.7,17 32.2,17 33.3,18.1 33.3,24.5 36.5,27.7 v36.5,28.7
A13  (via drill 0.2)
  Top 0.127: IC3.34 53.5,44.1 51.9,42.5 51.9,36.3 50.1,34.5 IC1.16 40.6,34.5 36,29.9 v36,29.5 | 31.45,17.5 v31.1,17.5 | IC4.4 31.45,17.5 | 31.45,17.5
  Bottom 0.127: v31.1,17.5 32.2,17.5 33,18.3 33,24.6 36,27.6 v36,29.5
A14  (via drill 0.2)
  Top 0.127: IC3.33 53,44 51.6,42.6 51.6,36.4 50.2,35 IC1.17 40.6,35 35.5,29.9 v35.5,28.8 | IC4.3 v31.7,18
  Bottom 0.127: v31.7,18 32.2,18 32.7,18.5 32.7,24.7 35.5,27.5 v35.5,28.8
A15  (via drill 0.2)
  Top 0.127: IC3.31 52,43.4 51.3,42.7 51.3,37.4 50.4,36.5 IC1.20 47.8,36.5 46.8,35.5 40.6,35.5 35.8,30.7 35.8,30.6 35,29.8 v35,29.5 | IC4.2 | IC4.2 v31.1,18.5
  Bottom 0.127: v31.1,18.5 32,18.5 32.4,18.9 32.4,24.8 35,27.4 v35,29.5
A16  (via drill 0.2)
  Top 0.127: IC3.28 50.5,43.8 51,43.3 51,37.6 50.4,37 IC1.21 47.6,37 46.6,36 38.9,36 35.3,32.4 v35.3,30.8 | IC4.1 v31.7,19
  Bottom 0.127: v35.3,30.8 34.4,29.9 34.4,27.2 32.1,24.9 32.1,19.4 v31.7,19
A17  (via drill 0.2)
  Top 0.127: IC3.27 50,43.9 50.7,43.2 50.7,38 v50.2,37.5 IC1.22 | IC4.48 | IC4.48 v53.6,19 | v52,31 52,34.2 v51.6,34.6
  Bottom 0.127: v51.6,34.6 51.6,36.1 v50.2,37.5 | v53.6,19 53.6,20.2 51.7,22.1 51.7,30.7 v52,31
A18  (via drill 0.2)
  Top 0.127: IC3.26 49.5,44 50.4,43.1 50.4,38.6 49.8,38 IC1.23 47.8,38 46.1,36.3 38.2,36.3 v37.5,35.6 | IC4.17 v41.5,11
  Bottom 0.127: v41.5,11 41.7,11.2 41.7,15.9 42.7,16.9 42.7,25.7 42.5,25.9 42.5,27 43.8,28.3 43.8,29.6 37.8,35.6 v37.5,35.6
A19  (via drill 0.2)
  Top 0.127: IC3.25 49,44.1 50.1,43 50.1,38.8 49.8,38.5 IC1.24 47.8,38.5 45.9,36.6 37.6,36.6 36.8,35.8 v36.8,35.1 | IC4.16 v38.3,11.5 | v38.3,11.5
  Bottom 0.127: v38.3,11.5 37.7,12.1 37.7,21.4 38.5,22.2 38.5,24.1 40.4,26 41,26 41.4,26.4 41.4,27 41.7,27.3 42.2,27.3 43.4,28.5 43.4,29.6 38,35 36.9,35 v36.8,35.1
A20  (via drill 0.2)
  Top 0.127: IC3.24 48.5,44.2 49.8,42.9 49.8,39.4 49.4,39 IC1.25 48.5,39 | 48.5,39 48.2,39 | 48.5,39 47.9,39 45.8,36.9 37.3,36.9 37,37.2 36.3,37.2 35,38.5 35,38.9 33.9,40 26.4,40 24.3,37.9 24.3,33.76 25.45,32.61 25.45,30.63 24.67,29.85 21.89,29.85 21.64,30.1 20.9,30.1 19.4,28.6 19.4,26.4 17.99,24.99 14.02,24.99 12.41,26.6 5.9,26.6 2.9,29.6 v2.9,30 S2.3 | IC11.2 8.2,36.4 v8.5,36.4 8.95,36.4 IC11.1
  Bottom 0.127: v2.9,30 8.5,35.6 v8.5,36.4
A20\
  Top 0.127: S2.1 2.04,33.49 2.05,33.5 2.8,33.5 3.6,34.3 6.85,34.3 IC11.4
A21
  Top 0.127: IC12.1 IC12.2 13,32.6 11.9,31.5 7.27,31.5 5.76,29.99 S2.6 5.59,29.99 7.38,28.2 12.99,28.2 13.87,27.32 13.87,25.91 14.48,25.3 17.8,25.3 19.1,26.6 19.1,28.7 19.7,29.3 19.7,34.6 20.4,35.3 20.4,36.5 20.9,37 23.8,37 24,37.2 24,38 26.3,40.3 34,40.3 35.3,39 35.3,38.6 36.4,37.5 37.1,37.5 37.4,37.2 45.7,37.2 47,38.5 IC1.26 48.85,40.6 49.5,41.25 49.5,42.8 48,44.3 IC3.23
A21\
  Top 0.127: S2.4 6.61,33.49 8,32.1 11.6,32.1 12.25,32.75 IC12.4
A22  (via drill 0.2)
  Top 0.127: IC1.29 45.5,39.7 45.7,39.5 v45.7,38.5 | v45.4,48.1 52,48.1 53.7,49.8 53.7,54.8 54,55.1 55.3,55.1 55.4,55 IC3.53
  Bottom 0.127: v45.7,38.5 45.7,45.5 45.4,45.8 v45.4,48.1
A23  (via drill 0.2)
  Top 0.127: IC3.5 39,45 v39,46.5 | v45,41.88 IC1.30
  Bottom 0.127: v39,46.5 40,46.5 40.7,47.2 41.4,47.2 42.8,45.8 42.8,44.08 v45,41.88
AC1
  Top 1.27: J2.1 84.31,28.45 84.3,27.9 | F1.1 76.85,27.9 84.3,27.9 | J102.1 92.25,28.73 91.55,27.9 84.3,27.9
AC2
  Top 0.61: D6.A D7.C 84.6,36.14 D1.A
  Top 1.27: 87.27,35.18 J2.3 87.31,35.2 87.3,35.2 84.99,32.89 D1.A
  Bottom 1.27: J2.3 90.3,30.5 J2.2 92.03,32.2 93.95,32.2 J102.2
ACF
  Top 0.61: D1.C 80.9,36.9 83.5,39.5 83.5,45.9 D4.A D5.C
  Top 0.813: F1.2 76.05,36.95 78.87,36.95 D1.C
ALARM#  (via drill 0.2)
  Top 0.127: v41,46.6 44.6,46.6 45,46.2 IC3.17 | v34.5,41.9 33.2,40.6 26.15,40.6 23.7,38.15 23.7,37.5 23.5,37.3 20.3,37.3 19.55,36.55 R2.1 19.4,35.65 19.4,29.86 19.4,29.46 17.91,27.96 IC7.3
  Bottom 0.127: v34.5,41.9 38.1,45.5 39.9,45.5 v41,46.6
ALEDA  (via drill 0.4)
  Top 0.127: R7.1 85.19,22.1 89.31,17.98 v92.05,17.98
  Bottom 0.127: J1.12 94.86,20.8 v92.05,17.98
ALEDC  (via drill 0.4)
  Top 0.127: IC14.6 77.45,18.55 78,18 79.5,18 80,18.5 80,20.2 81.05,21.25 85.2,21.25 90.3,16.15 v92.05,16.15
  Bottom 0.127: J1.11 95.2,19.31 v92.05,16.15
ATCK  (via drill 0.2)
  Top 0.127: RN6.1 41.2,22.95 41.55,23.3 v41.75,23.3 41.75,23.5 42.5,24.25 IC1.91
  Bottom 0.127: JP5.6 29.3,2.9 35.3,2.9 40.1,7.7 40.1,17.7 41.8,19.4 41.8,23.25 v41.75,23.3
ATDI  (via drill 0.2)
  Top 0.127: IC1.89 41.5,24.3 v41.6,24.2 41.6,23.95 40.4,22.75 RN6.2
  Bottom 0.127: JP5.19 15.4,4.8 36.4,4.8 39.5,7.9 39.5,21.4 41.2,23.1 41.2,23.8 v41.6,24.2 41.4,24
ATDO  (via drill 0.2)
  Top 0.127: v41.95,26.7 42,26.65 IC1.90
  Bottom 0.127: v41.95,26.7 41.95,25.85 42.4,25.4 42.4,17 41,15.6 41,7.8 35.5,2.3 19.9,2.3 JP5.16
ATMS  (via drill 0.2)
  Top 0.127: JP5.5 29.7,7.1 36.2,7.1 37.1,8 v38.6,8 | IC1.88 41,24.2 v40.65,23.85 40.4,23.85 39.6,23.05 RN6.3
  Bottom 0.127: v38.6,8 39.2,8.6 39.2,21.6 40.65,23.05 v40.65,23.85
AVCC3  (via drill 0.2, 1)
  Top 0.127: v77.6,7.4 R21.2 | R20.2 v79.78,12.34
  Top 0.254: C27.1 74.38,4.62 73.75,5.25 73.75,6.25 73.5,6.5 IC2.27 72.47,6.97 72.5,7 IC2.28 | IC2.35 v73.95,10.5
  Top 0.508: C28.1 75.1,10.5 v73.95,10.5 | C27.1 v75.4,4.6
  Top 1.016: FB2.1 v82.67,2.73
  pour Supply (isolate 0.254, no thermals): 69.85,11.43 69.85,2.54 85.09,2.54 85.09,13.97 83.19,13.97 83.19,13.34 76.83,13.34 76.83,11.43
BA20  (via drill 0.2)
  Top 0.127: IC4.9 | v31.7,15 IC4.9 | S2.2 2.79,31.74 3.5,31.03 3.5,29.6 6,27.1 v13.2,27.1
  Bottom 0.127: v31.7,15 30.8,15 30.3,15.5 30.3,19.2 24.4,25.1 14.7,25.1 13.2,26.6 v13.2,27.1
BA21  (via drill 0.2)
  Top 0.127: IC4.10 | v31.1,14.5 31.4,14.5 | 31.4,14.5 IC4.10 | 31.4,14.5 | v12.4,27.6 6.1,27.6 4.1,29.6 4.1,31.4 4.44,31.74 S2.5
  Bottom 0.127: v31.1,14.5 30.9,14.5 30,15.4 30,18.5 23.7,24.8 14.2,24.8 12.4,26.6 v12.4,27.6
BIAS
  Top 0.127: R24.2 72.47,4.47 | 72.47,4.47 IC2.26 | 72.47,4.47 72.45,4.45
CAR0  (via drill 0.2)
  Top 0.127: 56.6,64 | 56.6,64 IC3.71 | 56.6,64 v57.6,64 58.8,65.2 58.8,69.8 61,72 61,73.62 J5.23 | v61.5,55.2 64.2,52.5 J4.19
  Bottom 0.127: v57.6,64 56.5,62.9 56.5,60.1 61.4,55.2 v61.5,55.2
CAR1  (via drill 0.2)
  Top 0.127: J5.24 59.49,72.39 57.6,70.5 54.7,70.5 54,69.8 54,66.9 | 54,66.9 | 54,66.9 IC3.74 54,65.05 v54.3,64.75 | v60.6,55.2 64.3,51.5 J4.21
  Bottom 0.127: v60.6,55.2 60.6,55.6 56.2,60 56.2,62.85 v54.3,64.75
CAR2  (via drill 0.2)
  Top 0.127: J5.25 58.5,73.58 58.5,72 57.3,70.8 54.5,70.8 53.5,69.8 IC3.75 v53.5,64.1 | v59.7,55.2 63.9,51 J4.22
  Bottom 0.127: v59.7,55.2 59.7,56.1 55.9,59.9 55.9,61.7 v53.5,64.1
CAR3
  Top 0.127: J5.26 55.86,71.1 54.35,71.1 53,69.75 53,66.9 | 53,66.9 | IC3.76 53,66.9
CAR4
  Top 0.127: J5.27 55.9,73.64 55.9,72 55.3,71.4 54.2,71.4 52.5,69.7 52.5,67.7 | IC3.77 52.5,67.7 | 52.5,67.7
CAR5
  Top 0.127: J5.28 52,69.78 52,66.7 | 52,66.7 | IC3.78 52,66.7
CAR6
  Top 0.127: J5.29 53.2,73.8 53.2,72 51.62,70.42 51.62,67.38 51.62,67.33 51.5,67.2 IC3.79
CAR7
  Top 0.127: J5.30 51.33,71.64 51.33,67.53 51,67.2 IC3.80
CAR8
  Top 0.127: J5.31 51.02,73.44 51.02,67.72 50.5,67.2 50.5,66.9 | 50.5,66.9 | IC3.81 50.5,66.9
CAR9
  Top 0.127: 50,66.75 | IC3.82 50,66.75 | 50,66.75 50,67.2 50.73,67.92 50.73,71.17 49.53,72.37 J5.32
CAR10
  Top 0.127: J5.33 48.3,73.62 48.3,72.1 50.42,69.97 50.42,68.12 49.5,67.2 49.5,66.65 | 49.5,66.65 | IC3.83 49.5,66.65
CAR11
  Top 0.127: IC3.85 48.5,66.5 48.5,67.3 48.1,67.7 48.1,69.03 46.99,70.14 J5.34
CAR12
  Top 0.127: J5.35 45.8,73.58 45.8,70.7 47.8,68.7 47.8,67.4 48,67.2 48,66.7 | 48,66.7 | IC3.86 48,66.7
CAR13
  Top 0.127: IC3.87 47.5,68.2 44.45,71.25 J5.36
CAR14
  Top 0.127: J5.37 43.2,73.64 43.2,71.8 47,68 IC3.88
CAR15
  Top 0.127: IC3.91 45.5,68.8 J5.38
CCTS  (via drill 0.2)
  Top 0.127: IC6.15 v83.75,64.85 | v54.4,50.5 54.45,50.5 | 54.45,50.5 IC3.44 | 54.45,50.5
  Bottom 0.127: v54.4,50.5 55.5,50.5 55.9,50.9 66.2,50.9 67.9,52.6 71.4,52.6 72.2,53.4 72.2,61.5 73,62.3 82.5,62.3 83.75,63.55 v83.75,64.85
CDCD  (via drill 0.2)
  Top 0.127: IC6.19 v81.15,64.85 | v54.4,52.5 54.45,52.5 | 54.45,52.5 IC3.48 | 54.45,52.5
  Bottom 0.127: v54.4,52.5 55.7,52.5 56.4,51.8 65.9,51.8 68.2,54.1 68.2,61.5 69.9,63.2 80.4,63.2 81.15,63.95 v81.15,64.85
CDR0
  Top 0.127: IC3.59 65.9,58 68.4,55.5 J4.13 71.75,55.5 73.5,57.25 73.5,68.2 71.2,70.5 71.2,73.58 J5.15
CDR1
  Top 0.127: IC3.60 66.3,58.5 68.8,56 J4.12 71.5,56 73.2,57.7 73.2,67.6 69.85,70.95 J5.16
CDR2
  Top 0.127: IC3.61 66.7,59 68.7,57 J4.10 71.75,57 72.9,58.15 72.9,67 68.6,71.3 68.6,73.64 J5.17
CDR3
  Top 0.127: IC3.64 66.1,60.5 69.1,57.5 J4.9 71.5,57.5 72.6,58.6 72.6,66.4 67.31,71.69 J5.18
CDR4
  Top 0.127: IC3.66 66,61.5 69,58.5 J4.7 71.75,58.5 72.3,59.05 72.3,65.8 66.1,72 66.1,73.6 J5.19
CDR5
  Top 0.127: IC3.68 65.9,62.5 69.4,59 J4.6 71.5,59 72,59.5 72,65.16 J5.20
CDR6
  Top 0.127: IC3.69 66.3,63 69.3,60 J4.4 71.5,60 71.7,60.2 71.7,64.6 65.1,71.2 64.2,71.2 63.6,71.8 63.6,73 62.23,74.37 J5.21
CDR7
  Top 0.127: IC3.70 62.4,63.5 | 62.4,63.5 66.7,63.5 69.7,60.5 J4.3 | J5.22 62.4,72.22 62.4,63.5
CDSR  (via drill 0.2)
  Top 0.127: IC6.17 v82.45,64.85 | v54.4,51.5 54.45,51.5 | 54.45,51.5 IC3.46 | 54.45,51.5
  Bottom 0.127: v54.4,51.5 66,51.5 68.5,54 68.5,61.4 70,62.9 80.75,62.9 82.45,64.6 v82.45,64.85
CDTR  (via drill 0.2)
  Top 0.127: IC6.12 82.45,60.95 v82.3,61.1 | IC3.40 | v55,48.5 IC3.40
  Bottom 0.127: v82.3,61.1 82,61.4 73.4,61.4 73.1,61.1 73.1,51.4 70.8,49.1 56.4,49.1 55.8,48.5 v55,48.5
CFON  (via drill 0.2)
  Top 0.127: IC6.23 78.55,65.82 v78.55,64.85 | v54.4,54.5 54.45,54.5 | 54.45,54.5 IC3.52 | 54.45,54.5
  Bottom 0.127: v54.4,54.5 55.5,54.5 57,53 65.5,53 67,54.5 67,61.9 70.7,65.6 77.8,65.6 v78.55,64.85
CLKA
  Top 0.127: IC5.10 57.77,30.43 58,30.65 R3.1
CLKB
  Top 0.127: IC5.9 56.52,31.07 56.2,31.4 55,31.4 54.25,30.65 R6.1
CLKC
  Top 0.127: IC5.1 61.98,26.52 R5.1
CLKD
  Top 0.127: IC5.7 63.83,30.43 64,30.6 64,33.2 63.8,33.4 R4.1
CLKOE  (via drill 0.2)
  Top 0.127: 56.25,55.5 | 56.25,55.5 IC3.54 | v53.1,55.5 56.25,55.5 | IC5.16 58.17,26.52 v58.3,26.4
  Bottom 0.127: v58.3,26.4 59.2,27.3 59.2,29.8 56.5,32.5 56.5,44.2 53.6,47.1 53.6,48.6 53.1,49.1 v53.1,55.5
CLKS2  (via drill 0.2)
  Top 0.127: IC5.15 58.17,27.18 v58.3,27.3 | v53.1,48.3 53.4,48 IC3.39
  Bottom 0.127: v58.3,27.3 58.9,27.9 58.9,29.7 56.2,32.4 56.2,44.1 53.1,47.2 v53.1,48.3
CNFOFF  (via drill 0.2)
  Top 0.127: IC6.22 79.2,64.5 78.8,64.1 76.45,64.1 v76.25,64.3 | v55,54 55.05,54 | 55.05,54 IC3.51 | 55.05,54
  Bottom 0.127: v55,54 55.4,54 56.7,52.7 65.6,52.7 67.3,54.4 67.3,61.8 69.6,64.1 76.05,64.1 v76.25,64.3
CNINVAL  (via drill 0.2)
  Top 0.127: IC6.21 v79.85,64.85 | v54.4,53.5 IC3.50 | v54.4,53.5
  Bottom 0.127: v54.4,53.5 55.5,53.5 56.6,52.4 65.7,52.4 67.6,54.3 67.6,61.7 69.7,63.8 79.05,63.8 79.85,64.6 v79.85,64.85
CPUCLK
  Top 0.127: IC1.82 38,24.5 38.3,24.2 38.3,21.7 38.6,21.4 41.54,21.4 41.83,21.11 41.83,20.73 42.16,20.4 48.8,20.4 49.7,21.3 51.9,21.3 52.5,21.9 53.6,21.9 54.3,22.6 54.3,27.85 54.25,27.9 R6.2
CRD  (via drill 0.2)
  Top 0.127: IC6.16 v83.1,64.15 | v55,51 55.05,51 | 55.05,51 IC3.45 | 55.05,51
  Bottom 0.127: v55,51 55.2,51.2 66.1,51.2 67.8,52.9 71.3,52.9 71.9,53.5 71.9,61.6 72.9,62.6 82.2,62.6 83.1,63.5 v83.1,64.15
CRI  (via drill 0.2)
  Top 0.127: IC6.20 v80.5,64.25 | v55,53 IC3.49 | v55,53
  Bottom 0.127: v55,53 55.6,53 56.5,52.1 65.8,52.1 67.9,54.2 67.9,61.6 69.8,63.5 79.75,63.5 v80.5,64.25
CRTS  (via drill 0.2)
  Top 0.127: IC6.14 v83.75,62 | v55,50 IC3.43 | v55,50
  Bottom 0.127: v55,50 55.55,50 56.15,50.6 66.3,50.6 67,51.3 71.6,51.3 72.5,52.2 72.5,61.4 73.1,62 v83.75,62
CTD  (via drill 0.2)
  Top 0.127: IC6.13 v83.1,61.5 | IC3.41 | v54.4,49 IC3.41
  Bottom 0.127: v83.1,61.5 82.9,61.7 73.2,61.7 72.8,61.3 72.8,51.5 70.7,49.4 54.8,49.4 v54.4,49
CTS  (via drill 0.2)
  Top 0.127: v78.4,55.1 RN2.3 | IC6.8 79.84,59.16 v79.85,59.05
  Bottom 0.127: v79.85,59.05 79.85,56.55 v78.4,55.1
D0  (via drill 0.2)
  Top 0.127: 44.5,44.9 | 44.5,44.9 IC3.16 | 44.5,44.9 44.5,44.38 44.38,44.25 44.38,41.5 44.5,41.38 IC1.31 44.5,39.5 v44.9,39.1 | v58.6,9.7 60.25,9.7 61.35,8.6 IC2.6 | v51.3,9.5 IC4.29
  Bottom 0.127: v44.9,39.1 44.9,35.4 49.1,31.2 49.1,20.2 51.5,17.8 51.5,9.7 v51.3,9.5 50.7,8.9 50.7,8.1 51,7.8 51.6,7.8 53.5,9.7 v58.6,9.7
D1  (via drill 0.2)
  Top 0.127: 52.5,10.5 v53.5,10.5 | IC4.31 52.5,10.5 | 52.5,10.5 v51,10.5 | 44,44.9 | 44,44.9 IC3.15 | 44,44.9 IC1.32 44,39.55 44.3,39.25 v44.3,38.3 | v58.6,10.5 59.95,10.5 61.85,8.6 IC2.7
  Bottom 0.127: v51,10.5 51.2,10.7 51.2,17.7 48.8,20.1 48.8,31.1 44.3,35.6 v44.3,38.3 | v53.5,10.5 53.9,10.1 58.2,10.1 v58.6,10.5
D2  (via drill 0.2)
  Top 0.127: v53.5,11.5 IC4.33 v50.7,11.5 | IC3.14 43.5,44.95 43.45,44.9 43.5,44.85 IC1.33 43.5,39.3 v43.7,39.1 | v58.6,11.5 59.45,11.5 62.35,8.6 IC2.8
  Bottom 0.127: v53.5,11.5 v58.6,11.5 | v50.7,11.5 50.9,11.7 50.9,17.6 48.5,20 48.5,31 43.7,35.8 v43.7,39.1
D3  (via drill 0.2)
  Top 0.127: v53.5,12.5 IC4.35 v50.4,12.5 | v43,38.3 IC1.34 43,44.9 | 43,44.9 | 43,44.9 IC3.13 | v58.6,12.5 58.95,12.5 62.85,8.6 IC2.9
  Bottom 0.127: v53.5,12.5 v58.6,12.5 | v50.4,12.5 50.6,12.7 50.6,17.5 48.2,19.9 48.2,30.9 43,36.1 v43,38.3
D4  (via drill 0.2)
  Top 0.127: IC4.38 52.4,14 v50.1,14 | v42.5,39.2 IC1.35 42.5,44.9 | 42.5,44.9 | 42.5,44.9 IC3.12 | v49.8,6.6 49.8,5.2 52.9,2.1 63.1,2.1 63.7,2.7 63.7,3.2 63.35,3.55 IC2.10
  Bottom 0.127: v49.8,6.6 49.9,6.7 49.9,13.8 v50.1,14 50.3,14.2 50.3,17.4 47.9,19.8 47.9,30.7 42.5,36.1 v42.5,39.2
D5  (via drill 0.2)
  Top 0.127: IC4.40 | v49.8,15 IC4.40 | v41.5,39.2 IC1.37 41.5,42.15 42,42.65 42,44.95 | 42,44.95 | 42,44.95 IC3.11 | v48.9,6.6 48.9,5.7 52.8,1.8 63.2,1.8 64,2.6 64,3.4 63.85,3.55 IC2.11
  Bottom 0.127: v48.9,6.6 49.6,7.3 49.6,14.8 v49.8,15 50,15.2 50,17.3 47.6,19.7 47.6,30.6 41.5,36.7 v41.5,39.2
D6  (via drill 0.2)
  Top 0.127: IC4.42 52.35,16 v49.5,16 | v41,38.3 IC1.38 41,42.05 41.62,42.67 41.62,44.25 41.5,44.38 41.5,44.85 41.45,44.9 41.5,44.95 IC3.10 | v48,6.6 48,6.2 52.7,1.5 63.3,1.5 64.35,2.55 IC2.12
  Bottom 0.127: v48,6.6 49.3,7.9 49.3,15.8 v49.5,16 49.7,16.2 49.7,17.2 47.3,19.6 47.3,30.5 41,36.8 v41,38.3
D7  (via drill 0.2)
  Top 0.127: IC4.44 | v49.2,17 IC4.44 | v40.5,39.2 IC1.39 40.5,41.95 41.25,42.7 41.25,44.12 41,44.38 41,44.8 | 41,44.8 | 41,44.8 IC3.9 | 53.55,17 v53.6,17 | IC4.44 53.55,17 | 53.55,17 | IC2.13 64.85,10.65 v58.5,17
  Bottom 0.127: v53.6,17 v58.5,17 | v49.2,17 49.2,17.3 47,19.5 47,30.4 40.5,36.9 v40.5,39.2
D8  (via drill 0.2)
  Top 0.127: v40,38.3 IC1.40 | v48.7,10 52.3,10 IC4.30 53.8,10 54,10.2 54,10.85 54.8,11.65 56.25,11.65 56.4,11.5 IC2.89
  Bottom 0.127: v48.7,10 48.7,17.4 46.7,19.4 46.7,30.3 40,37 v40,38.3
D9  (via drill 0.2)
  Top 0.127: v39.5,39.2 IC1.41 | v48.2,11 52.35,11 IC4.32 53.75,11 54.8,12.05 57.17,12.05 IC2.88
  Bottom 0.127: v48.2,11 48.4,11.2 48.4,17.3 46.4,19.3 46.4,30.2 39.5,37.1 v39.5,39.2
D10  (via drill 0.2)
  Top 0.127: IC2.87 54.4,12.5 53.9,12 IC4.34 52.4,12 v47.6,12 | v39,38.3 IC1.42
  Bottom 0.127: v47.6,12 48.1,12.5 48.1,17.2 46.1,19.2 46.1,30.1 39,37.2 v39,38.3
D11  (via drill 0.2)
  Top 0.127: 57.15,13 IC2.86 | 57.15,13 IC4.36 52.3,13 v47.6,13 | 57.15,13 | v38.5,39.2 IC1.43
  Bottom 0.127: v47.6,13 47.8,13.2 47.8,17.1 45.8,19.1 45.8,30 38.5,37.3 v38.5,39.2
D12  (via drill 0.2)
  Top 0.127: v37.5,39.2 IC1.45 | v47.3,14.5 IC4.39 55.1,14.5 56.1,13.5 IC2.85
  Bottom 0.127: v47.3,14.5 47.5,14.7 47.5,17 45.5,19 45.5,29.9 37.5,37.9 v37.5,39.2
D13  (via drill 0.2)
  Top 0.127: v37,38.3 IC1.46 | v47,15.5 IC4.41 53.1,15.5 53.3,15.7 53.3,16 53.5,16.2 54.9,16.2 55.6,15.5 55.6,14.8 56.4,14 IC2.84
  Bottom 0.127: v47,15.5 47.2,15.7 47.2,16.85 45.2,18.85 45.2,29.8 37,38 v37,38.3
D14  (via drill 0.2)
  Top 0.127: v36.5,39.2 IC1.47 | v46.7,16.5 IC4.43 55,16.5 55.9,15.6 55.9,15 56.4,14.5 IC2.83
  Bottom 0.127: v46.7,16.5 46.7,16.9 44.9,18.7 44.9,29.7 36.5,38.1 v36.5,39.2
D15  (via drill 0.2)
  Top 0.127: v36,38.6 IC1.48 36,42.4 36.8,43.2 36.95,43.2 37.5,43.75 37.5,45.05 | v45.3,17.5 IC4.45 54.4,17.5 56.2,15.7 56.2,15.2 56.4,15 IC2.82 | 37.5,45.05 | 37.5,45.05 IC3.2
  Bottom 0.127: v45.3,17.5 44.6,18.2 44.6,29.6 36,38.2 v36,38.6
DC  (via drill 0.2)
  Top 0.127: IC8.5 79.89,44.31 79.9,44.3 79.91,44.31 IC8.4
  Top 0.406: IC8.5 C2.1
  Top 0.61: C2.1 D4.C v82.4,44.8 D6.C
  Bottom 1.27: J5.10 77.47,70.2 90.5,70.2 95,65.7 95,57.65 95.02,57.63 R101.2 95.02,50.12 89.7,44.8 v82.4,44.8
DCD
  Top 0.127: RN1.4 78.7,50 76.6,52.1 76.6,57.35 77.25,57.99 IC6.4
DSR
  Top 0.127: IC6.6 78.55,59.8 78.55,58.8 77.4,57.65 77.4,56.2 76.9,55.7 76.9,52.6 78.7,50.8 RN1.3
DTR
  Top 0.127: IC6.11 81.8,58.52 81.76,58.52 80.4,57.16 80.4,56.1 80.2,55.9 RN2.2
ETHWAIT  (via drill 0.2)
  Top 0.127: IC2.4 60.35,5.75 v60.7,6.1 | v58.3,23.8 IC13.1
  Bottom 0.127: v60.7,6.1 60.7,6.9 60.2,7.4 60.2,16.8 57.8,19.2 57.8,23.3 v58.3,23.8
FBUSY  (via drill 0.2)
  Top 0.127: IC3.119 33.3,59.5 v32.8,59 | IC4.15 v31.7,12
  Bottom 0.127: v32.8,59 32.8,57.8 33.5,57.1 33.5,56.1 32.8,55.4 30.6,55.4 28.2,53 28.2,40.9 28.9,40.2 28.9,36 29.1,35.8 29.1,30.7 30.3,29.5 30.3,19.6 30.6,19.3 30.6,16.1 31.2,15.5 32,15.5 32.3,15.2 32.3,12.6 v31.7,12
GND  (via drill 0.2, 1)
  Top 0.254: v75,52.7 C9.2 | IC3.89 46.5,67.6 v46.25,67.6 46,67.6 IC3.90 | IC3.29 51,46.3 v50.8,46.5 | S1.S1 2.2,39.21 2.2,39.2 v4.85,39.2 | 50.15,36 IC1.19 | 50.15,36 v50.2,36 | IC1.18 50.15,35.5 50.15,36 | IC1.36 v42,41.85 | J4.2 v70.1,61 | J4.5 v70.1,59.5 | J4.8 v70.1,58 | J4.17 v69.75,53.5 | J4.20 v69.8,52 | 69.75,50.5 v69.8,50.5 J4.23 | C49.2 10.4,36.1 v10.05,36.45 | v12.35,36.4 12.35,36.45 | IC3.72 v56.3,65.2 | IC2.32 71.2,9 v71.2,8.75 71.2,8.5 IC2.31 | IC2.15 v65.85,5.65 | IC2.18 67.35,5.65 v67.6,5.65 67.85,5.65 IC2.19 | IC1.2 v49.9,27.5 | IC4.46 | IC4.46 v53.6,18 | IC2.81 v58.5,15.5 | IC2.76 56.35,18 56.05,18.3 v56.05,18.5 | IC2.63 64.85,18.65 v64.6,18.4 64.35,18.65 IC2.64 | IC2.58 v67.35,18.35 | IC2.48 v71.2,17 | C38.2 33.75,47 34.8,47 | 34.8,47 IC3.144 | IC1.52 34.65,38.5 v34.65,38 IC1.53 | C29.2 v43.8,21.35 C32.2 | J4.11 v70.1,56.5 | J4.14 v70.1,55 | v32.15,32 IC1.65 | IC5.11 56.23,29.77 C18.2 v56,30.7 | v39.8,24.1 40,24.3 IC1.86 IC1.87 | v61.35,40.35 61.35,40.1 63.58,40.1 IC9.7 | IC2.25 70.85,3.05 v71,2.9 C21.2 69.85,3 IC2.23 | IC3.108 v36.3,66.3 | IC3.36 v54.5,43.8 | IC4.27 53.35,8.5 53.75,8.1 v53.85,8.1 | 34.8,47 v34.8,46.3 | v41.5,64.9 IC3.99 | v41.5,64.9 | IC6.25 v77.25,64.81 v77.25,64.8 | C19.2 55.65,9.1 56.05,9.5 IC2.93 | C19.2 55.8,9.05 55.85,9 IC2.94 | C19.2 56.2,8.5 IC2.95 58.4,8.5 58.4,8 | C36.2 45.15,43.7 45.5,44.05 IC3.18 | IC3.114 v36.6,62 | v36.6,62 | IC3.123 v36.6,57.5 | v36.6,57.5 | 55.8,52 | 55.8,52 IC3.47 57.75,52 C40.2 | v55,52 55.8,52 | IC3.62 | IC3.62 v57.8,59.5 | C33.2 35.65,23.6 36,23.95 IC1.78 | IC2.99 58.4,6.5 58.4,8 | 58.4,8 IC2.96 | IC5.3 64.12,27.82 v64.15,27.8 | IC15.2 13,40.7 v12.7,41 12.25,40.55 IC15.3 | IC14.2 v75.3,17.8
  Top 0.305: S1.C1 6.21,40.56 v4.85,39.2
  Top 0.406: J6.C 28.75,69.15 v29.15,69.55 | C43.2 v30.65,64.9 | R17.1 79.45,40.45 79.8,40.45 IC8.2 v79.8,43 | C4.2 74.85,47.7 v76.1,47.7 76.45,47.7 76.75,47.4 D8.A 78.1,47.4 78.6,47.9 C2.2 | v76.1,47.05 75.3,47.05 | D7.A v81.6,41.9 | IC10.2 v17.9,39.2
  Top 0.508: v77.35,12.05 76.45,12.05 C22.2 76.35,11.6 76.6,11.35 76.6,10.7 C28.2 | C7.2 78.79,13.87 v79.78,13.87 | C8.2 80.45,5.53 v80.45,6.7 | v71,2.9 R24.1 C27.2 74.4,2.88 | C6.2 v78.5,69 | v78.5,67.35 C51.2 | v29.4,49.6 30.05,48.95 C30.2 | v28.1,33.98 28.1,33.95 28.27,34.12 C26.2 | C34.2 v28.1,32.8 | C44.2 55.08,69.55 v56.2,69.55 | C39.2 48.8,70.1 v47.85,70.1 | R18.2 23.2,38.25 v23.2,37.9 | v28.75,55.12 28.75,55.15 29.73,55.15 C5.2 | C42.2 31.65,56.25 v31.9,56.5 | v37.7,43.25 38.05,43.6 38.62,43.6 C41.2 38.65,43.3 39.4,42.55 C35.2 | C47.2 34.2,43.75 v34.2,44.7 | v55.2,8 55.65,8.45 C19.2 | v45.12,42.62 45.1,42.65 45.1,43.52 C36.2 | v48.62,41.12 48.65,41.15 48.65,42.05 C31.2 | C20.2 63.1,2.9 v63.15,2.95 | C16.2 54.65,15.45 v55.1,15 | C46.2 v59,48.6 | v35.95,22.55 35.65,22.85 C33.2 | C37.2 50.6,33.85 v50.9,34.15 | 64.22,23.75 64.25,23.75 | 64.22,23.75 v64.22,23.73 | C17.2 64.22,23.75 | v58.5,22.2 58.4,22.1 C25.2 | C23.2 v70.45,22.1 | C45.2 v59.05,54.15 | R9.1 v54,40 | C48.2 v15.2,41.05 | v12.35,36.4 12.25,36.3 IC12.3 | C50.2 v15.2,36.4 | IC11.3 7.45,36.3 v7.55,36.4 | R14.1 v31.1,23.5
  Top 0.61: C2.2 D5.A | C10.2 v61.35,40.35 C11.2 | v67.6,64.7 J4.G1 | v67.6,46.8 J4.G2
  Top 1.016: J6.6 21.8,61.72 v21.8,61.7 | 21.8,54.22 v21.8,54.25 | J6.3 21.8,54.22 | 21.8,54.22 21.8,54.2
  Ground 0.127: 12.7,2.54 12.65,2.52 12.6,2.55
  other vias: 71.2,14 61.35,39.2 67.94,28.57 72.71,22.61 72.71,37.15 60.8,29.8 60.8,26.4 62.1,27.8 64.2,29.8 58.2,24.6 57,22.8 63.8,6 60.3,18.1 68.11,42.7 22,34.6 43.8,19.7 55,26.2
  pour Ground (isolate 0.305): 7.62,77.47 7.62,41.91 3.17,41.91 3.17,8.26 12.7,8.26 12.7,2.54 83.19,2.54 83.19,13.34 80.01,13.34 80.01,36.83 85.72,36.83 85.72,48.26 82.55,48.26 82.55,57.78 88.9,57.78 88.9,59.69 85.72,59.69 85.72,69.22 89.53,69.22 89.53,77.47
  pour Top (isolate 0.203): 0.64,41.91 27.3,41.91 27.3,25.4 0.64,25.4
  pour Top (isolate 0.203): 53.34,43.18 68.58,43.18 68.58,37.47 73.03,37.47 73.03,5.4 53.34,5.4
  pour Top (isolate 0.305): 34.29,23.5 34.29,19.05 48.9,19.05 48.9,23.5
LLEDA  (via drill 0.4)
  Top 0.127: R8.1 79.6,17.15 80.4,17.95 80.4,20 81.2,20.8 84.8,20.8 91.27,14.33 v92.05,14.33
  Bottom 0.127: J1.9 96.47,9.39 96.47,11.73 93.88,14.33 v92.05,14.33
LLEDC  (via drill 0.2, 0.4)
  Top 0.127: IC14.4 76.65,17.05 77.5,16.2 v77.5,13.75
  Bottom 0.127: J1.10 93.38,11.17 v92.05,12.5 91.75,12.19 83.29,12.19 82.14,13.34 80.77,13.34 80.54,13.11 78.14,13.11 v77.5,13.75
MCD  (via drill 0.2)
  Top 0.127: 34.8,59 | 34.8,59 IC3.120 | v33.8,59 34.8,59 | RN4.2 v31.7,53.3 | v31.45,69.3 29.7,69.3 28.43,68.03 J6.CD
  Bottom 0.127: v31.7,53.3 34.4,56 34.4,58.4 v33.8,59 32.8,60 32.8,67.95 v31.45,69.3
MCLK
  Top 0.127: J6.5 18.73,59.22 18.75,59.2 29.8,59.2 31.1,57.9 32.7,57.9 34.1,56.5 35,56.5 | 35,56.5 | 35,56.5 IC3.125
MCMD  (via drill 0.2)
  Top 0.127: v31.9,59 RN5.3 | IC3.126 34.2,56 32.8,57.4 v31.9,57.4 30.4,55.9 26.8,55.9 22.62,51.72 J6.2
  Bottom 0.127: v31.9,57.4 v31.9,59
MDAT0
  Top 0.127: J6.7 21.05,64.15 25.2,60 RN5.1 30.3,59.2 31.3,58.2 32.8,58.2 34,57 35,57 | 35,57 | 35,57 IC3.124
MDAT1
  Top 0.127: J6.8 21.02,65.78 25.8,61 30.9,61 31.1,60.8 RN5.2 31.1,58.9 31.5,58.5 IC3.121
MDAT2  (via drill 0.2)
  Top 0.127: v30.1,53.3 RN4.4 | v30.1,53.3 30.1,53.5 30.5,53.9 33.62,53.9 34.23,54.5 34.75,54.5 | 34.75,54.5 | 34.75,54.5 IC3.129 | J6.9 20.02,46.72 26.6,53.3 v30.1,53.3
MDAT3  (via drill 0.2)
  Top 0.127: 34.8,55 | 34.8,55 IC3.128 | v30.9,53.3 RN4.3 | 34.8,55 34.25,55 33.75,54.5 v30.9,54.5 30.62,54.5 30,53.88 25.98,53.88 21.32,49.22 J6.1
  Bottom 0.127: v30.9,54.5 v30.9,53.3
MWP  (via drill 0.2)
  Top 0.127: 34.8,54 | 34.8,54 IC3.130 | 34.8,54 34.2,54 33.3,53.1 32.7,53.1 32.5,52.9 RN4.1 32.5,51.7 32.1,51.3 v26.2,51.3 | J6.WP 27.67,43.4 v26.2,43.4
  Bottom 0.127: v26.2,43.4 v26.2,51.3
N$1
  Top 0.254: C6.1 75.2,69 74.8,68.6 74.8,65.1 75.1,64.8 75.7,64.8 75.95,65.05 75.95,65.85 75.94,65.86 IC6.27
N$2
  Top 0.254: IC6.3 76.59,59.7 76.6,59.7 76.6,57.95 76,57.35 76,56.45 C9.1
N$3
  Top 0.254: IC6.2 75.94,59.8 75.95,59.8 75.95,58.05 C15.2
N$5
  Top 0.127: S1.C2 9.44,37.86 10.5,36.8 11.6,36.8 12.25,37.45 IC15.4
N$8
  Top 0.254: IC6.1 75.3,59.1 C15.1
N$9
  Top 0.254: IC6.24 77.9,66.85 C14.2
N$10
  Top 0.254: IC6.28 75.3,66.85 C14.1
N$13
  Top 0.406: IC8.3 80.75,40.4 R17.2 R19.1
N$18
  Top 0.254: C12.1 57.45,38.8 58.12,39.48 IC9.3
N$19
  Top 0.254: C12.2 57.45,40.8 58.12,40.12 IC9.2
N$21
  Top 0.254: C13.1 64.8,39.5 63.62,39.5 IC9.6
N$23
  Top 0.254: C13.2 64.9,40.8 63.62,40.8 IC9.8
N$45
  Top 0.127: Y1.2 66.4,26.85 64.78,28.48 IC5.4
N$46
  Top 0.127: Y1.1 66.4,30.75 64.78,29.12 IC5.5
N$49
  Top 0.127: S1.A1 1.95,40.95 2.4,41.4 10.2,41.4 10.8,40.8 R25.1
N$50
  Top 0.127: R26.1 1.95,36.45 1.9,36.5 1.95,36.55 S1.A2
NCRD
  Top 0.127: IC3.57 65.1,57 68.1,54 J4.16 71.75,54 74.1,56.35 74.1,69.4 73.7,69.8 73.7,73.62 J5.13
NCS0  (via drill 0.2)
  Top 0.127: v38,46.5 IC3.3 | v51.32,8.5 51.3,8.5 51.8,8 IC4.26 | v40.8,26.7 41.4,27.3 44.8,27.3 45.5,26.6 IC1.97 45.5,24.6 48,22.1 v49.6,22.1
  Bottom 0.127: v40.8,26.7 40.8,26.9 41.6,27.7 41.9,27.7 43,28.8 43,29.6 38,34.6 36.4,34.6 36.2,34.8 36.2,35.4 36.5,35.7 36.5,36.1 36.1,36.5 36.1,37.4 34,39.5 34,43.4 35,44.4 35,45.1 36.4,46.5 v38,46.5 | v51.32,8.5 51.8,8.98 51.8,17.9 49.4,20.3 49.4,21.9 v49.6,22.1
NCS1  (via drill 0.2)
  Top 0.127: IC2.3 59.9,4.42 v59.9,6.5 | IC1.98 46,24.6 47.9,22.7 v52.8,22.7
  Bottom 0.127: v59.9,6.5 59.9,16.6 53.8,22.7 v52.8,22.7
NCWAIT  (via drill 0.2)
  Top 0.127: v47,46.5 IC3.21 | v47,46.5 | v54,42.2 55,41.2 55,34.6 v53.9,33.5 | IC13.3 57.95,25.3 v58.1,25.45
  Bottom 0.127: v47,46.5 48.8,46.5 53.1,42.2 v54,42.2 | v53.9,33.5 53.9,31 52.6,29.7 52.6,25.85 53,25.45 v58.1,25.45
NCWR
  Top 0.127: IC3.58 65.5,57.5 68.5,54.5 J4.15 71.5,54.5 73.8,56.8 73.8,68.8 72.39,70.21 J5.14
NFBYTE  (via drill 0.2)
  Top 0.127: IC4.47 v54.2,18.5 | v53.35,42.75 53.35,41.55 52.8,41 52.8,32 v53,31.8 | v47.5,47.2 47.5,47.1 | 47.5,47.1 IC3.22 | 47.5,47.1
  Bottom 0.127: v54.2,18.5 54.2,20 52,22.2 52,30.2 53,31.2 v53,31.8 | v47.5,47.2 48.9,47.2 v53.35,42.75
NICCLK
  Top 0.127: IC2.22 69.35,7.95 58.7,18.6 58.4,18.6 57.6,19.4 57.6,22.2 59.15,23.75 R5.2
NLEDA\
  Top 0.127: IC2.62 65.35,18.55 66.4,17.5 70.6,17.5 71.7,18.6 73.3,18.6 73.7,18.2 73.7,17.35 74,17.05 IC14.3 74.5,15.25 R13.1
NLEDB\
  Top 0.127: 66.35,18.3 IC2.60 | 66.35,18.3 66.35,18.25 66.8,17.8 70.3,17.8 71.5,19 73.45,19 73.9,18.55 IC14.1 74.5,18.6 74.55,18.65 R12.1 | 66.35,18.3 66.3,18.3 65.85,18.75 IC2.61
NMR  (via drill 0.2)
  Top 0.127: IC10.4 16.6,39.6 16.2,39.2 11.7,39.2 | S1.S2 v9.3,39.2 11.7,39.2 | v39,47.3 37.3,47.3 35.75,45.75 32.85,45.75 R27.1 C30.1 30.05,45.15 29.8,44.9 15.6,44.9 11.7,41 11.7,39.2 | v40,47.3 IC3.7 | v40,47.3
  Bottom 0.127: J5.9 76.24,73.7 41.45,73.7 40.7,72.95 40.7,48 v40,47.3 v39,47.3 | v9.3,39.2 9.3,35.4 8.4,34.5 8.4,19.54 J7.6
NOE  (via drill 0.2)
  Top 0.127: v41.8,9.7 42,9.5 50.5,9.5 51,9 IC4.28 v53.85,9 | v60.75,8.3 v59.2,8.3 58.85,7.95 IC2.1 | IC3.6 39.5,45 39.5,47.6 39.8,47.9 41.8,47.9 42.3,47.4 45.8,47.4 46.2,47.8 52,47.8 52.3,47.5 v54.5,47.5 | v43,26.7 IC1.92 | v53.85,9
  Bottom 0.127: v43,26.7 43,16.8 42,15.8 42,9.9 v41.8,9.7 | 60.8,8.35 v60.75,8.3 61,8.55 61,22.85 59.5,24.35 59.5,29.9 58.95,30.45 58.95,43.05 v54.5,47.5 | v53.85,9 58.5,9 v59.2,8.3
NRESET  (via drill 0.2)
  Top 0.127: 35.25,47.5 | 35.25,47.5 IC3.143 | IC10.1 R18.1 20.55,38.85 20.8,39.1 24.2,39.1 26,40.9 29.1,40.9 v29.5,41.3 | IC4.12 | IC4.12 35.8,13.5 v36,13.3 42.8,13.3 44.5,15 44.5,17.7 44.9,18.1 50.4,18.1 51.7,19.4 53,19.4 53.2,19.6 54,19.6 54.8,18.8 54.8,17.5 56.3,16 IC2.80 | 35.25,47.5 34.4,47.5 34.15,47.75 29.4,47.75 29.1,47.45 29.1,45.9 v29.4,45.6 | v32.3,25.8 34,25.8 34.9,26.7 36.1,26.7 36.5,26.3 IC1.79 36.5,22.2 v36,21.7
  Bottom 0.127: v36,13.3 v36,21.7 | v32.3,25.8 32.3,30.7 30,33 30,36.12 29.8,36.33 29.8,41 v29.5,41.3 29.4,41.4 v29.4,45.6
NWAIT  (via drill 0.2)
  Top 0.127: IC1.96 45,24.6 48,21.6 50,21.6 50.6,22.2 53.2,22.2 53.5,22.5 53.5,22.9 53.25,23.15 R16.2 53.25,24.45 v53.7,24.9 | v55.5,22.85 IC13.6 55,23.8 54.7,24.1 54.7,25 55,25.3 IC13.4
  Bottom 0.127: v55.5,22.85 55.5,23.1 v53.7,24.9
NWE  (via drill 0.2)
  Top 0.127: IC4.11 v42.5,14 | v59.4,5.65 59.4,4.42 IC2.2 59.35,3.55 59.1,3.3 58.65,3.3 58.4,3.55 58.4,4.4 57.4,5.4 56.4,5.4 55.4,6.4 50.8,6.4 49.5,7.7 47.5,7.7 46.9,8.3 v42.5,8.3 | v54.2,60.6 36.3,60.6 36.2,60.5 IC3.117 | v59.35,46.75 59.6,47 v59.6,53.6 | IC1.93 43.5,26.4 v43.8,26.7
  Bottom 0.127: v42.5,8.3 v42.5,14 43.3,14.8 43.3,24.6 43.8,25.1 v43.8,26.7 | v59.6,53.6 57,53.6 54.2,56.4 v54.2,60.6 | v59.4,5.65 59.85,5.2 60.7,5.2 61.3,5.8 61.3,22.95 59.8,24.45 59.8,30 59.35,30.45 v59.35,46.75
P0  (via drill 0.2)
  Top 0.127: IC1.49 35.5,42.1 34.8,42.8 33.5,42.8 32.8,42.1 30.9,42.1 30.6,42.4 28.8,42.4 28.5,42.1 v26.2,42.1
  Bottom 0.127: J5.47 30.5,73.64 30.5,72 29.8,71.3 29.3,71.3 25.7,67.7 25.7,42.6 v26.2,42.1
P1  (via drill 0.2)
  Top 0.127: IC1.50 35,42.15 34.65,42.5 33.7,42.5 32.9,41.7 30.7,41.7 30.4,42 29,42 28.5,41.5 v25.7,41.5
  Bottom 0.127: J5.48 29.21,71.61 25.4,67.8 25.4,41.8 v25.7,41.5
P2  (via drill 0.2)
  Top 0.127: IC1.51 27,39 v26.6,39.4
  Bottom 0.127: J5.49 27.9,73.7 27.9,72 25.1,69.2 25.1,40.9 v26.6,39.4
P3  (via drill 0.2)
  Top 0.127: J5.50 27.76,71.3 32.3,71.3 33.8,69.8 38.4,69.8 41,67.2 IC3.100 | IC1.54 32.5,37.5 31.4,38.6 v26.4,38.6
  Bottom 0.127: J5.50 24.8,70.52 24.8,40.2 v26.4,38.6
P4  (via drill 0.2)
  Top 0.127: IC3.101 40.5,67.2 38.2,69.5 33.6,69.5 32.1,71 26.5,71 25.4,72.1 25.4,74 24.47,74.93 J5.51 | IC1.55 32.4,37 31.6,37.8 v26.2,37.8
